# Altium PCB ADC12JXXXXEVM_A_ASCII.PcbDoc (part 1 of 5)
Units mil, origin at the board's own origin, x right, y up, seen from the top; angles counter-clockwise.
Board outline 5739 x 2680 mil, 10 copper layers (Top Layer L1, Gnd-Plane - L2, Signals - L3, Gnd-Plane - L4, Pwr Plane - L5, Signals - L6, Gnd-Plane - L7, Signals - L8, Gnd-Plane - L9, Bottom Layer - L10), stack 57.8 mil thick; 582 components, 343 nets, 1924 pads, 1318 vias.
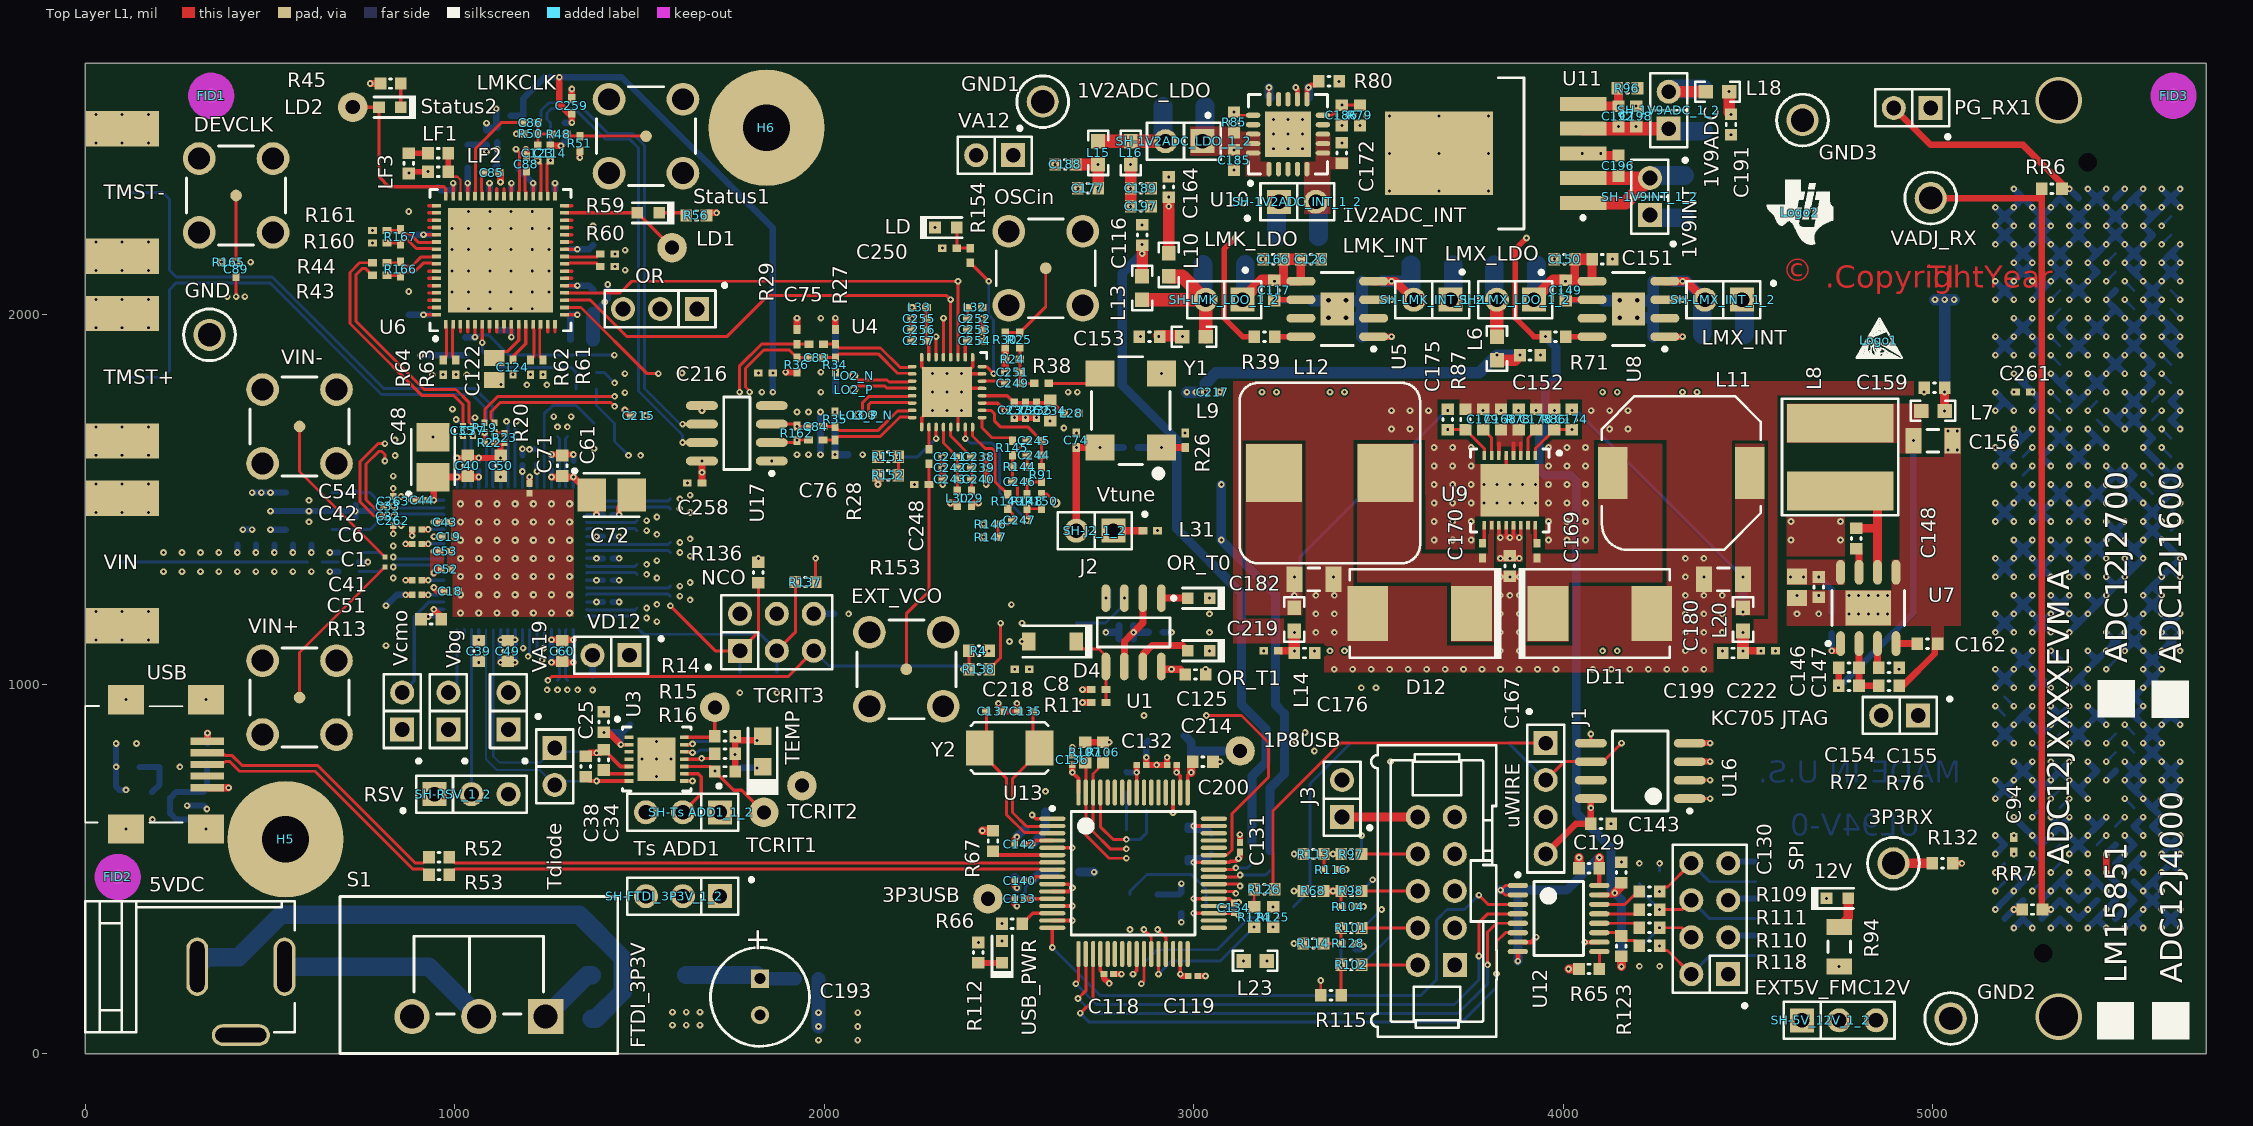
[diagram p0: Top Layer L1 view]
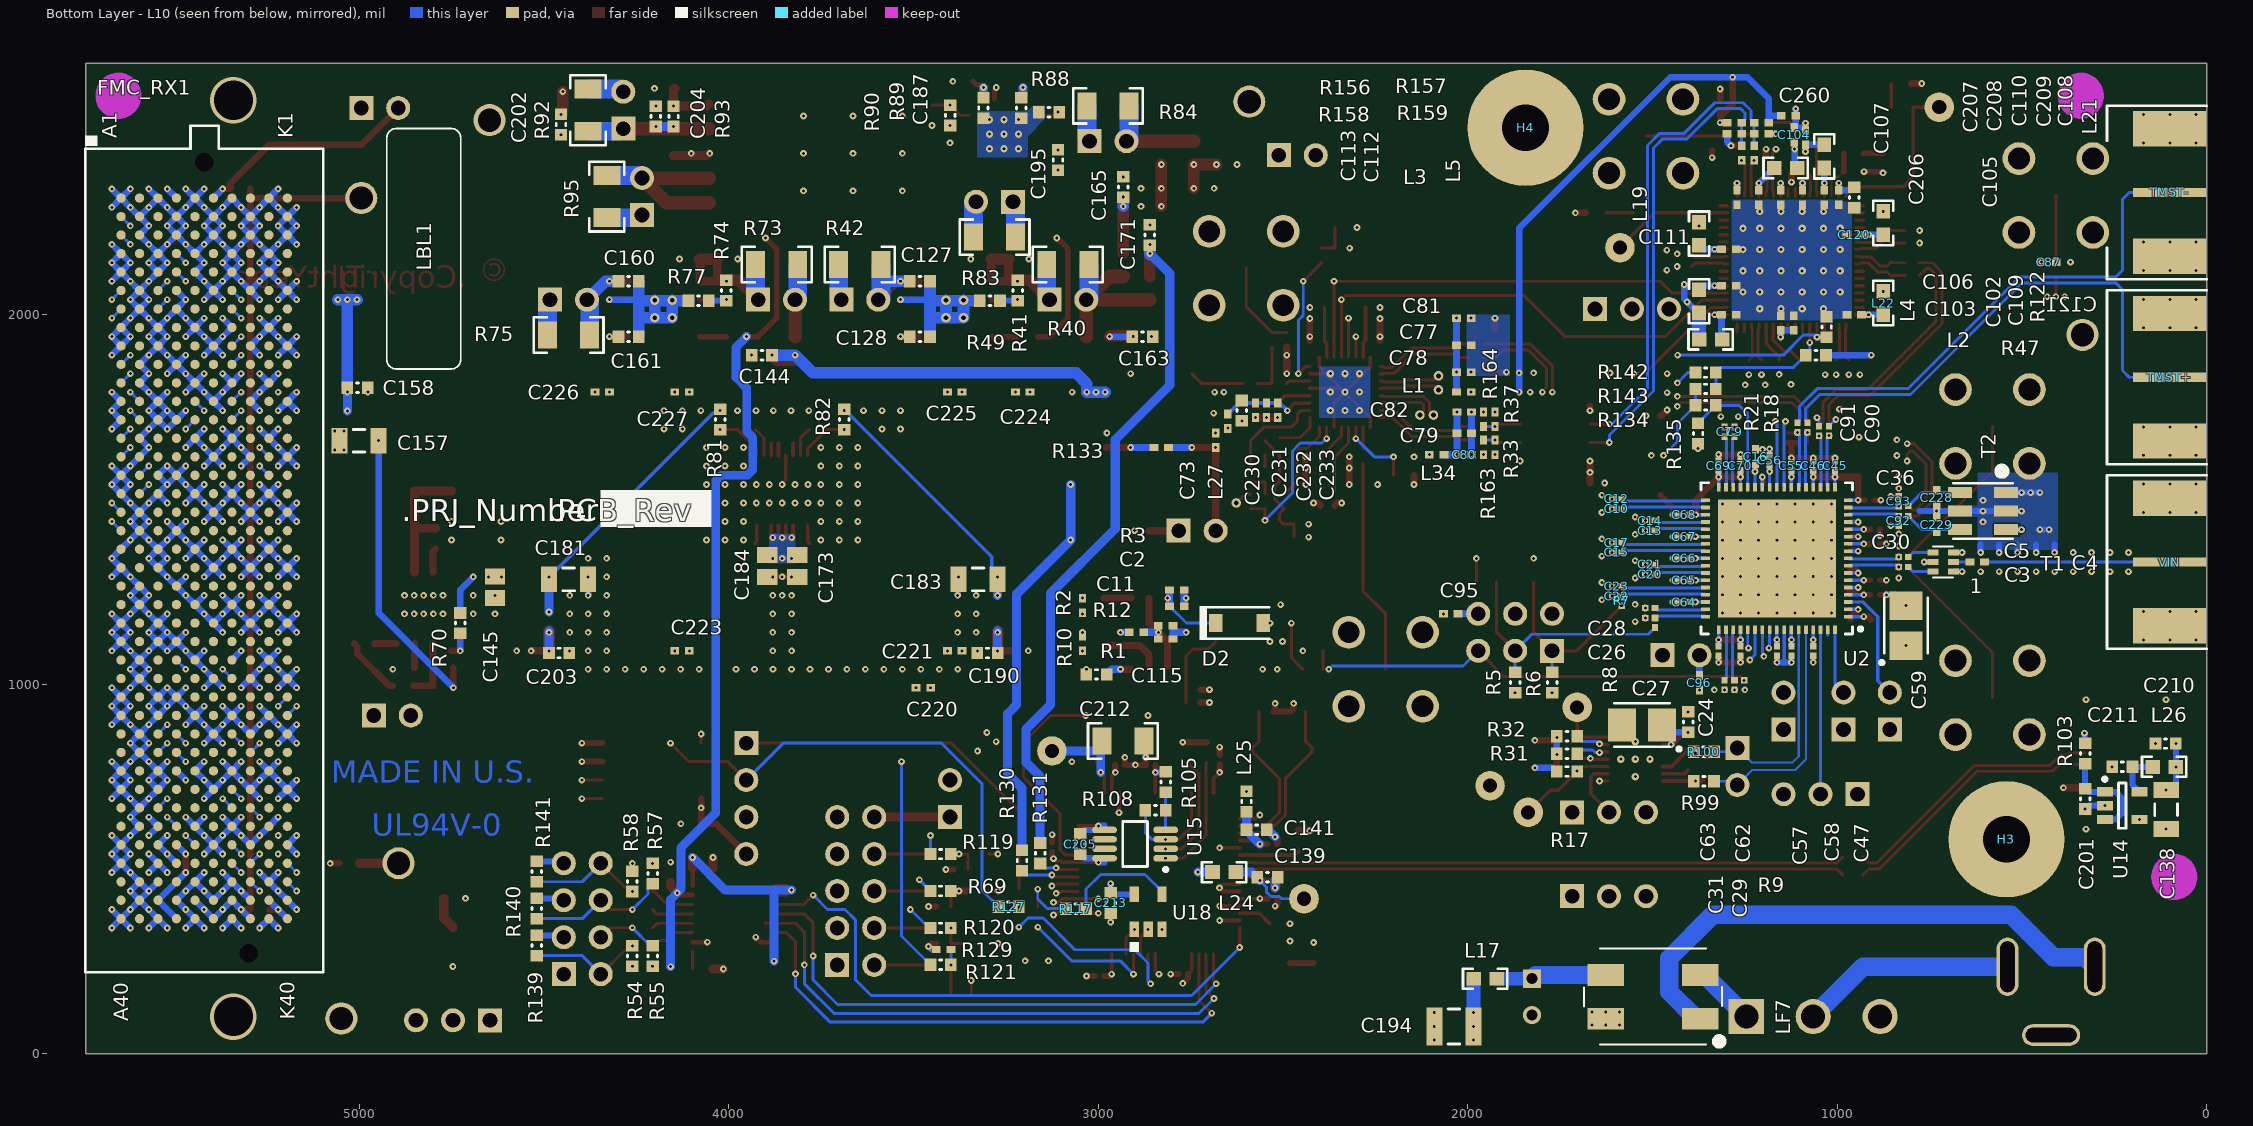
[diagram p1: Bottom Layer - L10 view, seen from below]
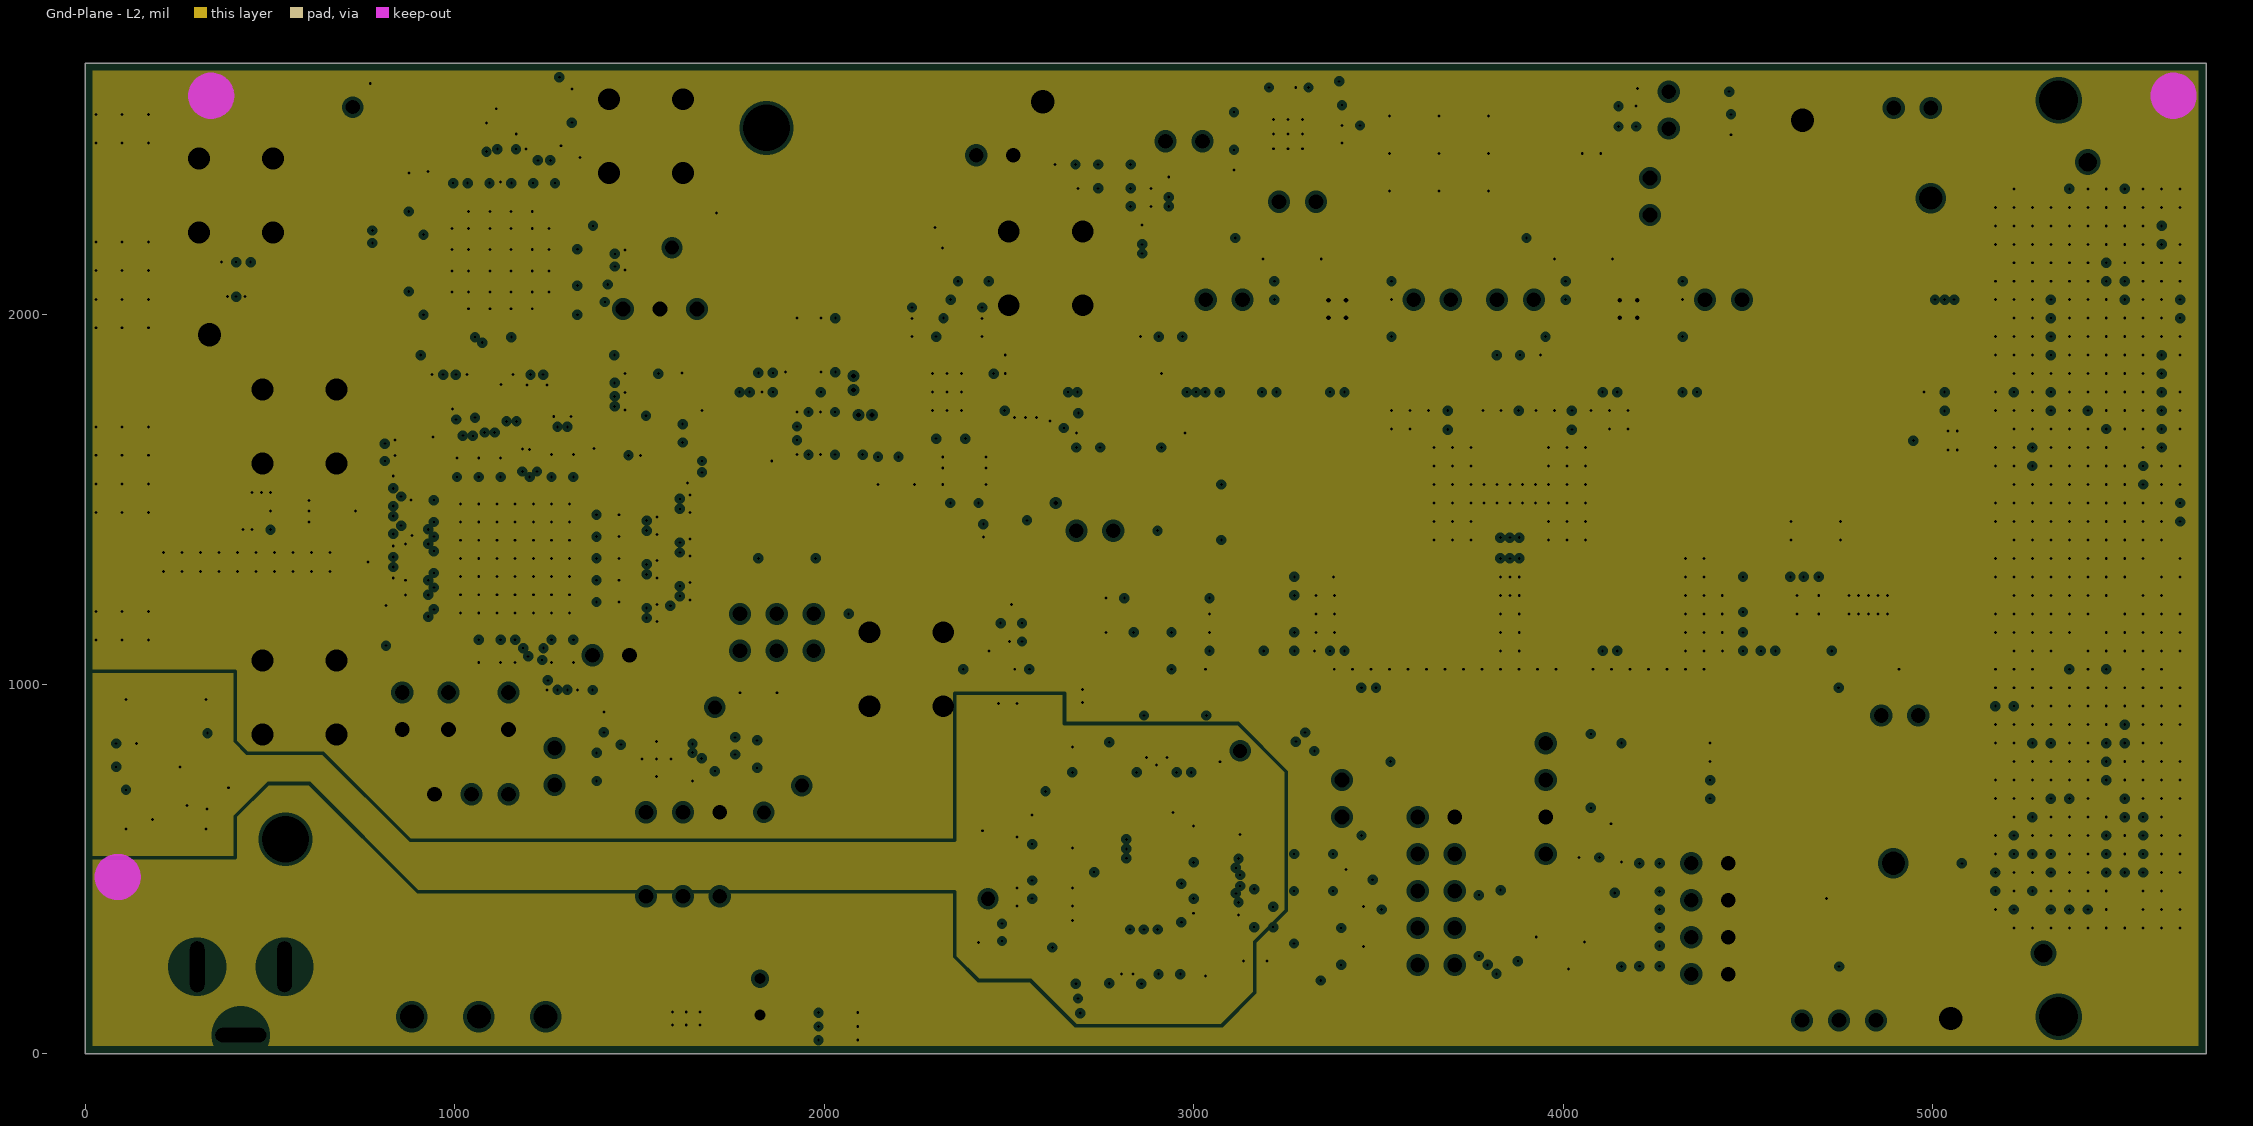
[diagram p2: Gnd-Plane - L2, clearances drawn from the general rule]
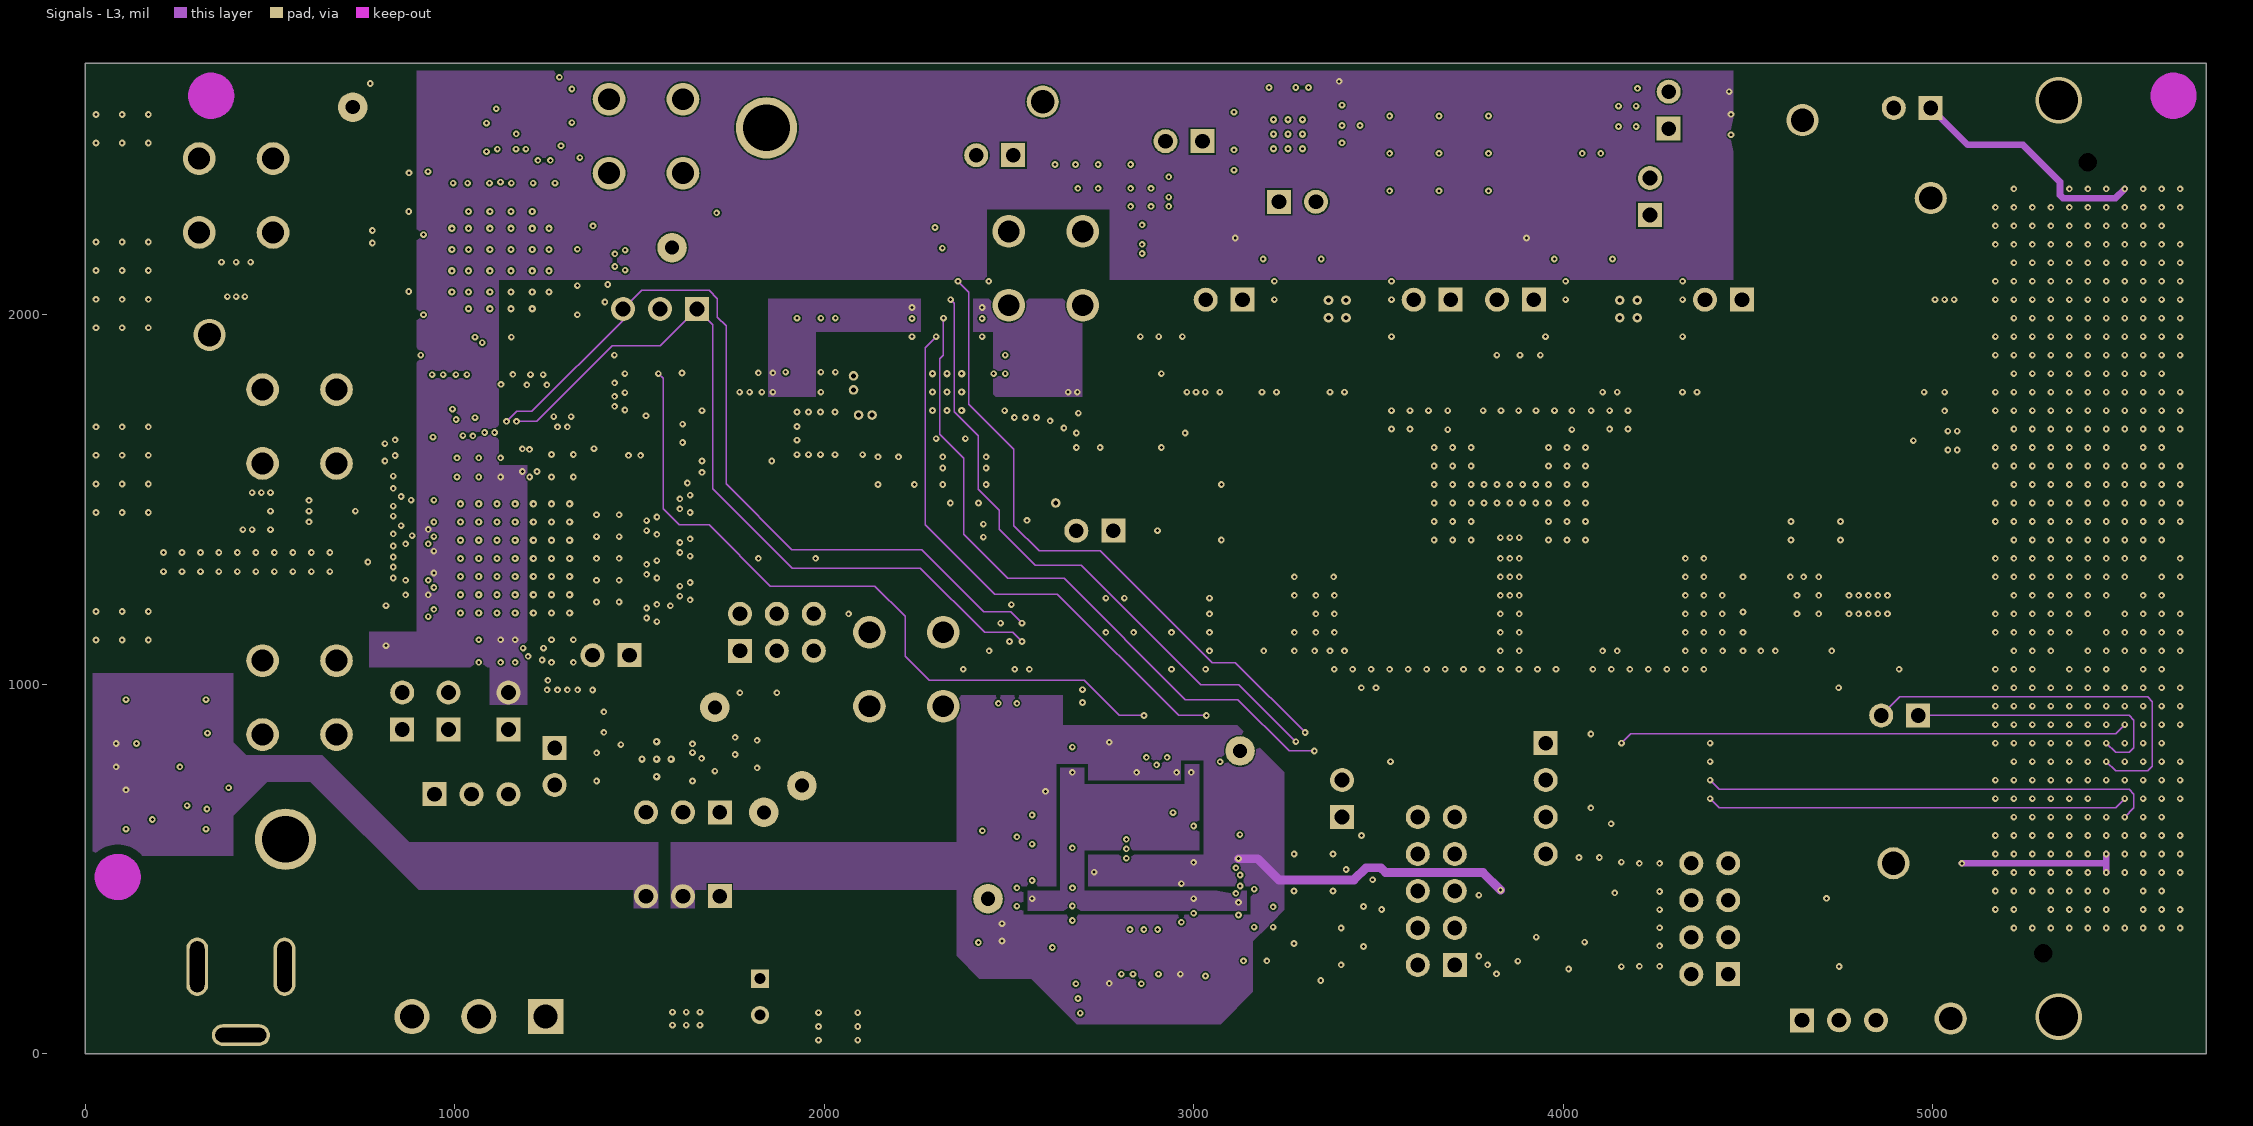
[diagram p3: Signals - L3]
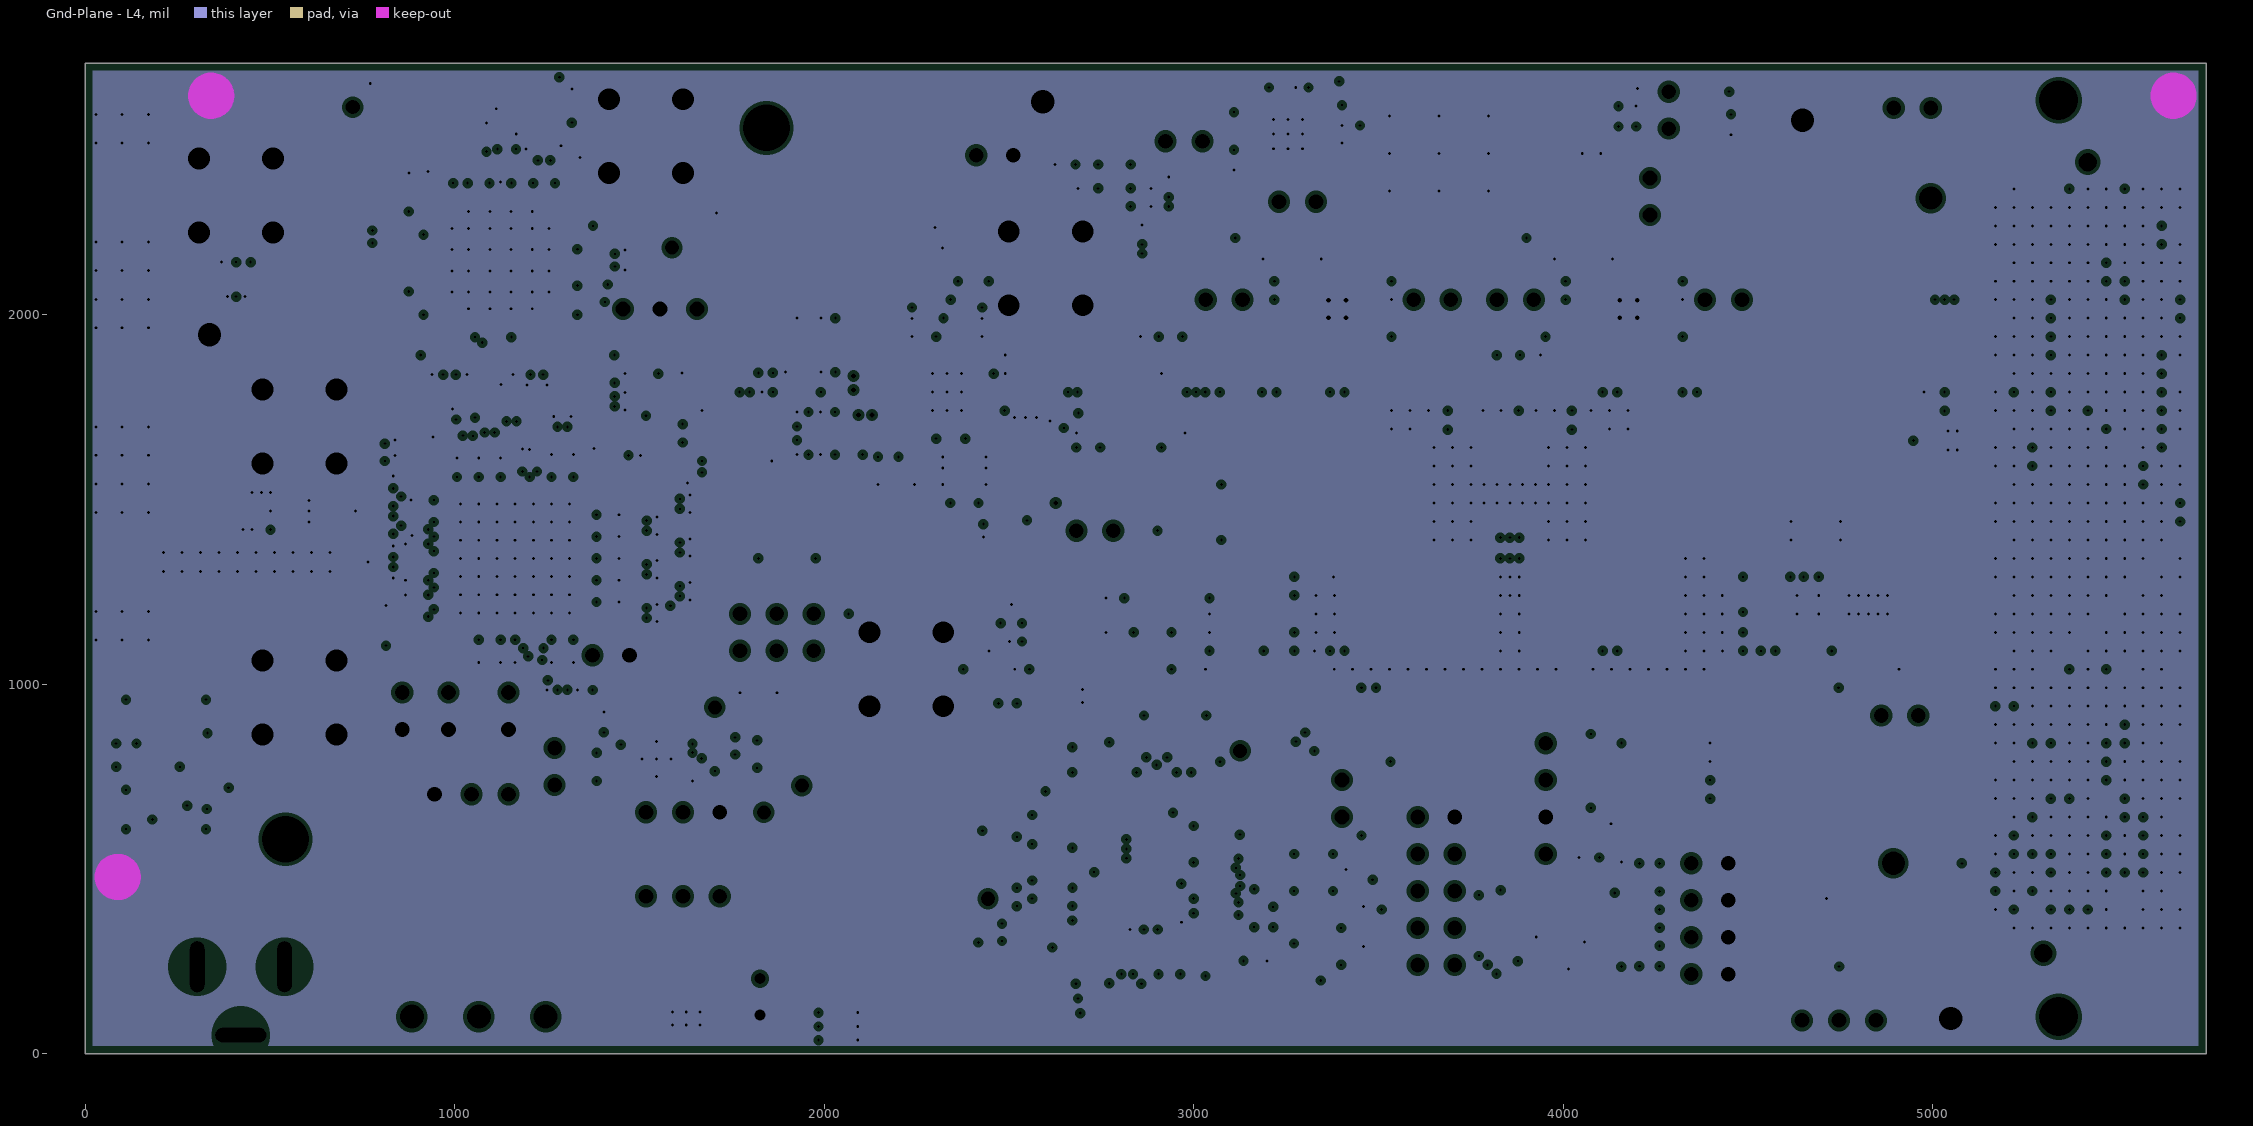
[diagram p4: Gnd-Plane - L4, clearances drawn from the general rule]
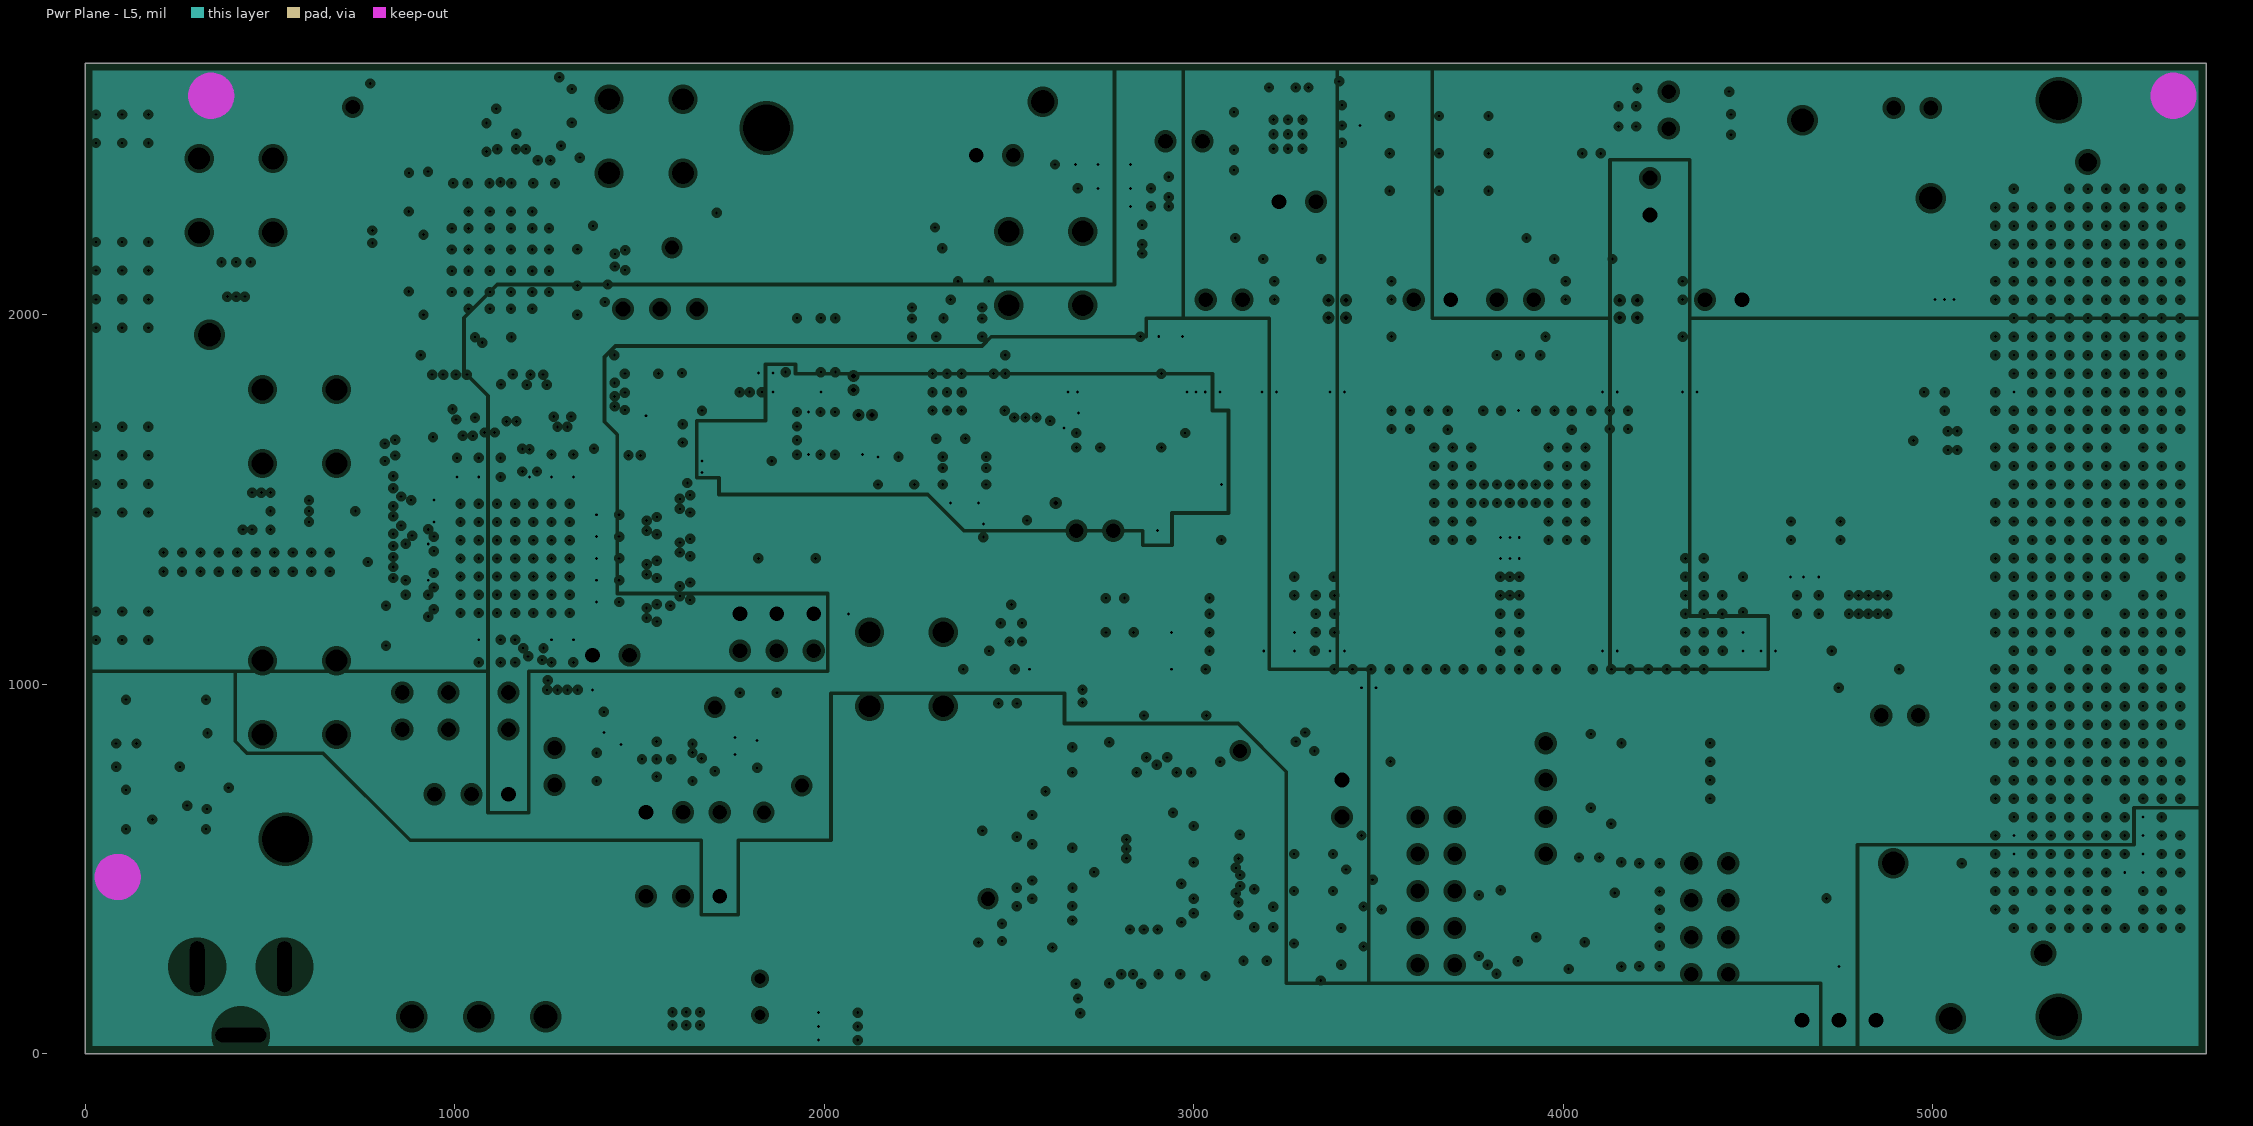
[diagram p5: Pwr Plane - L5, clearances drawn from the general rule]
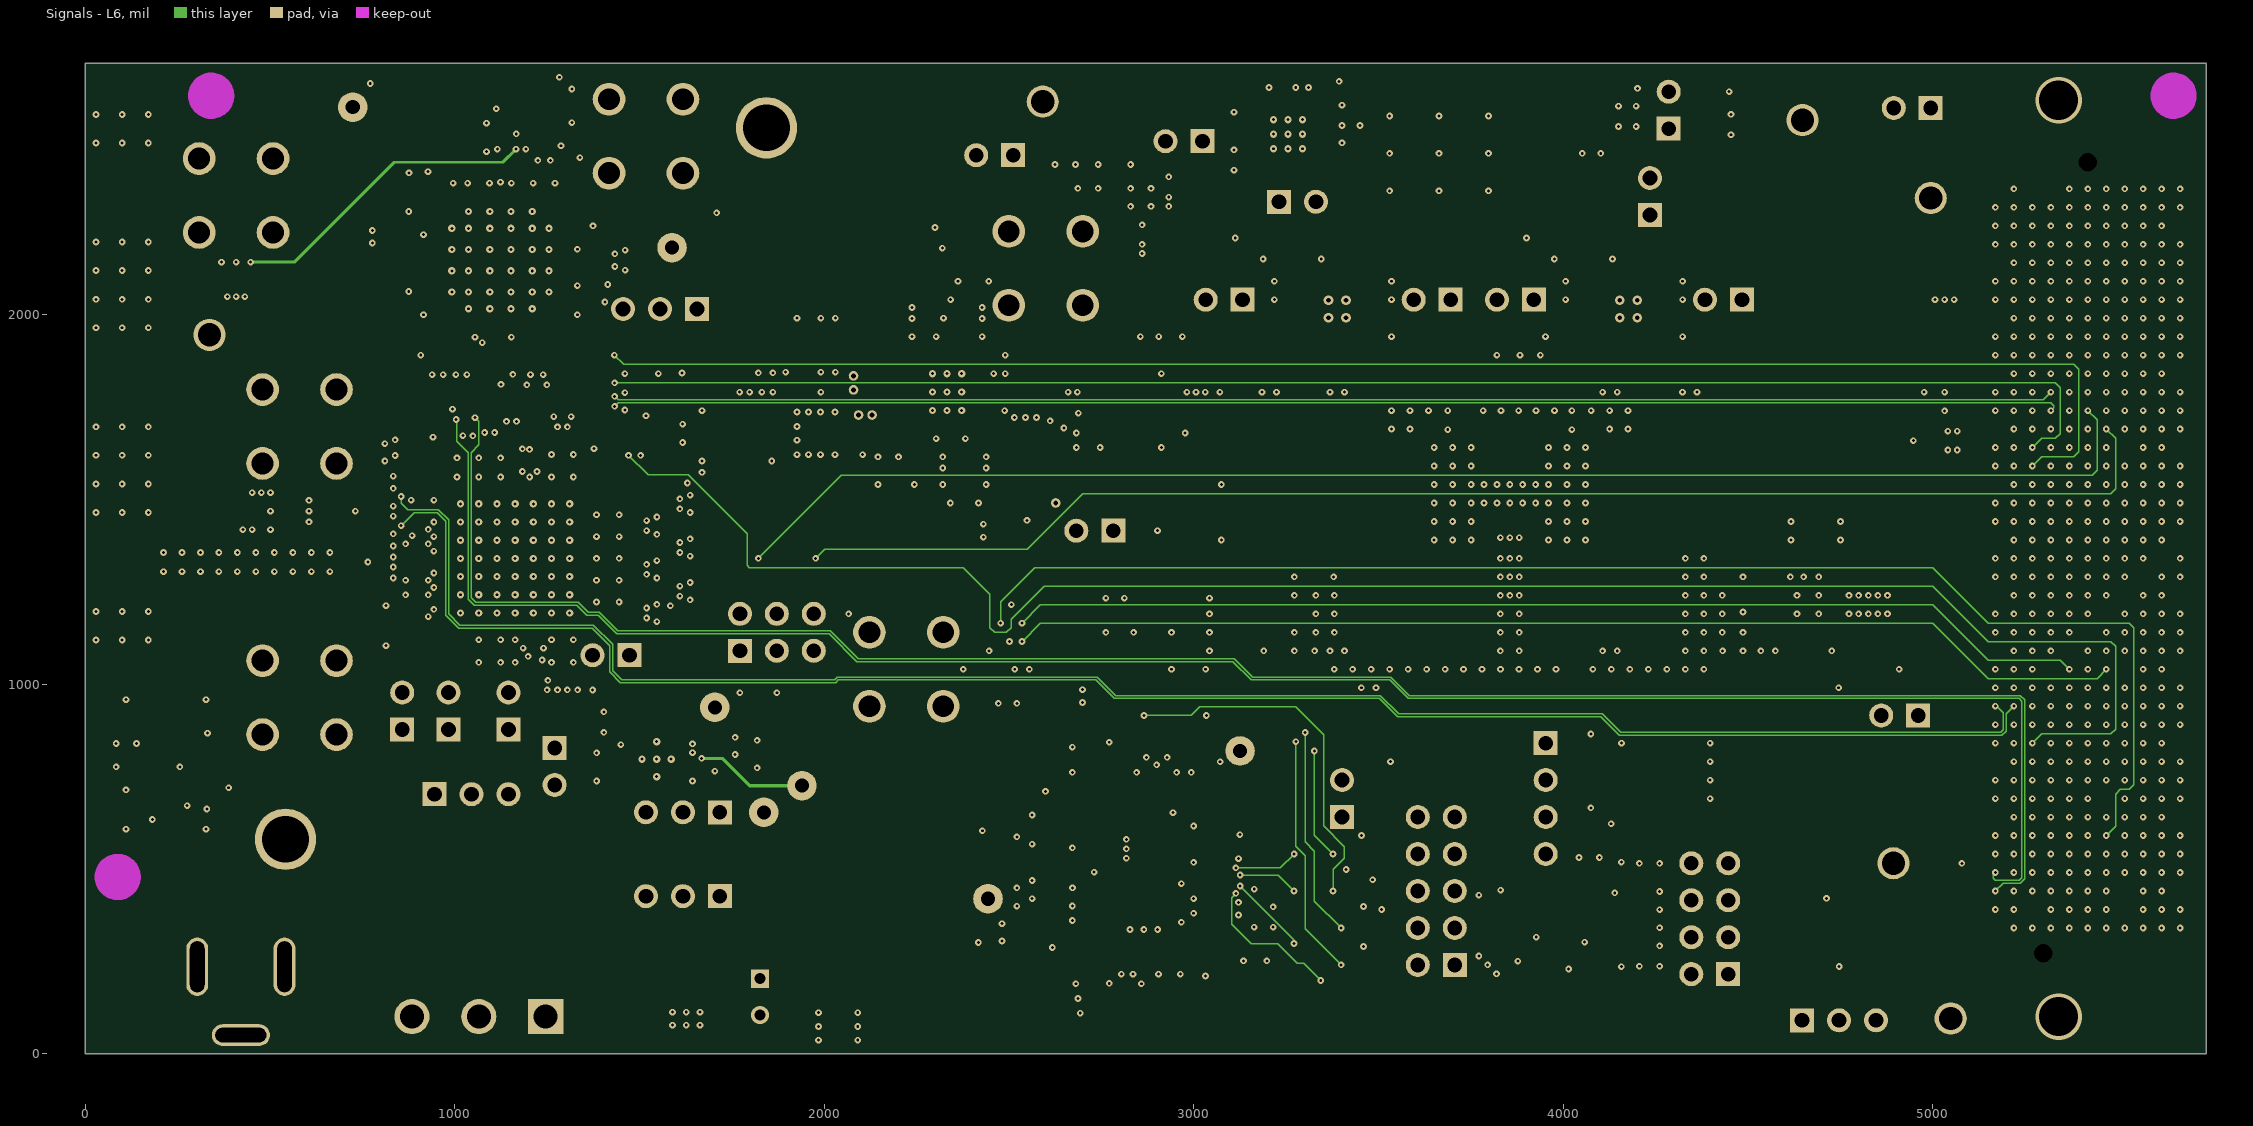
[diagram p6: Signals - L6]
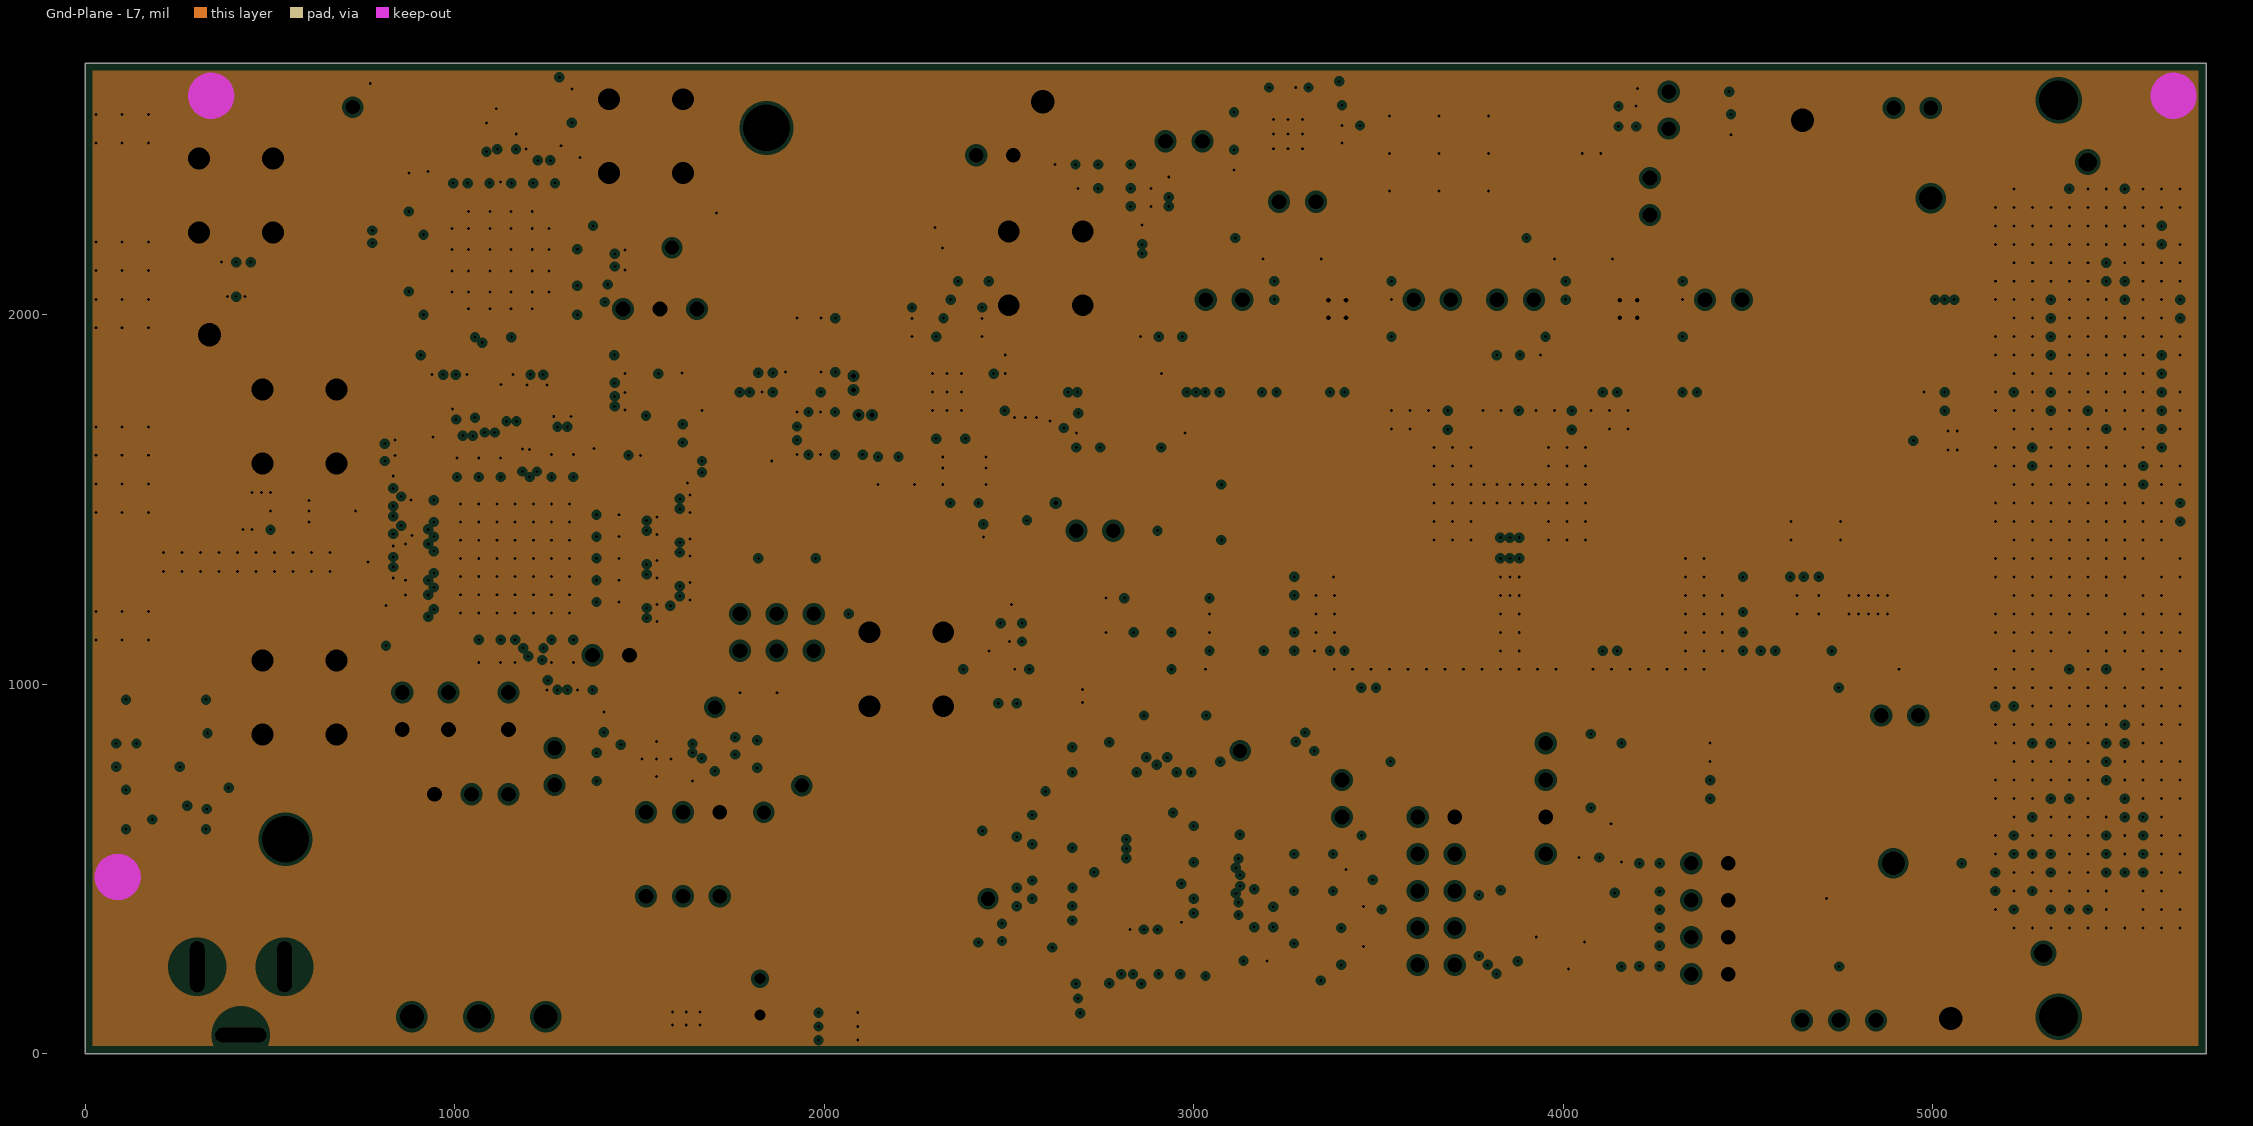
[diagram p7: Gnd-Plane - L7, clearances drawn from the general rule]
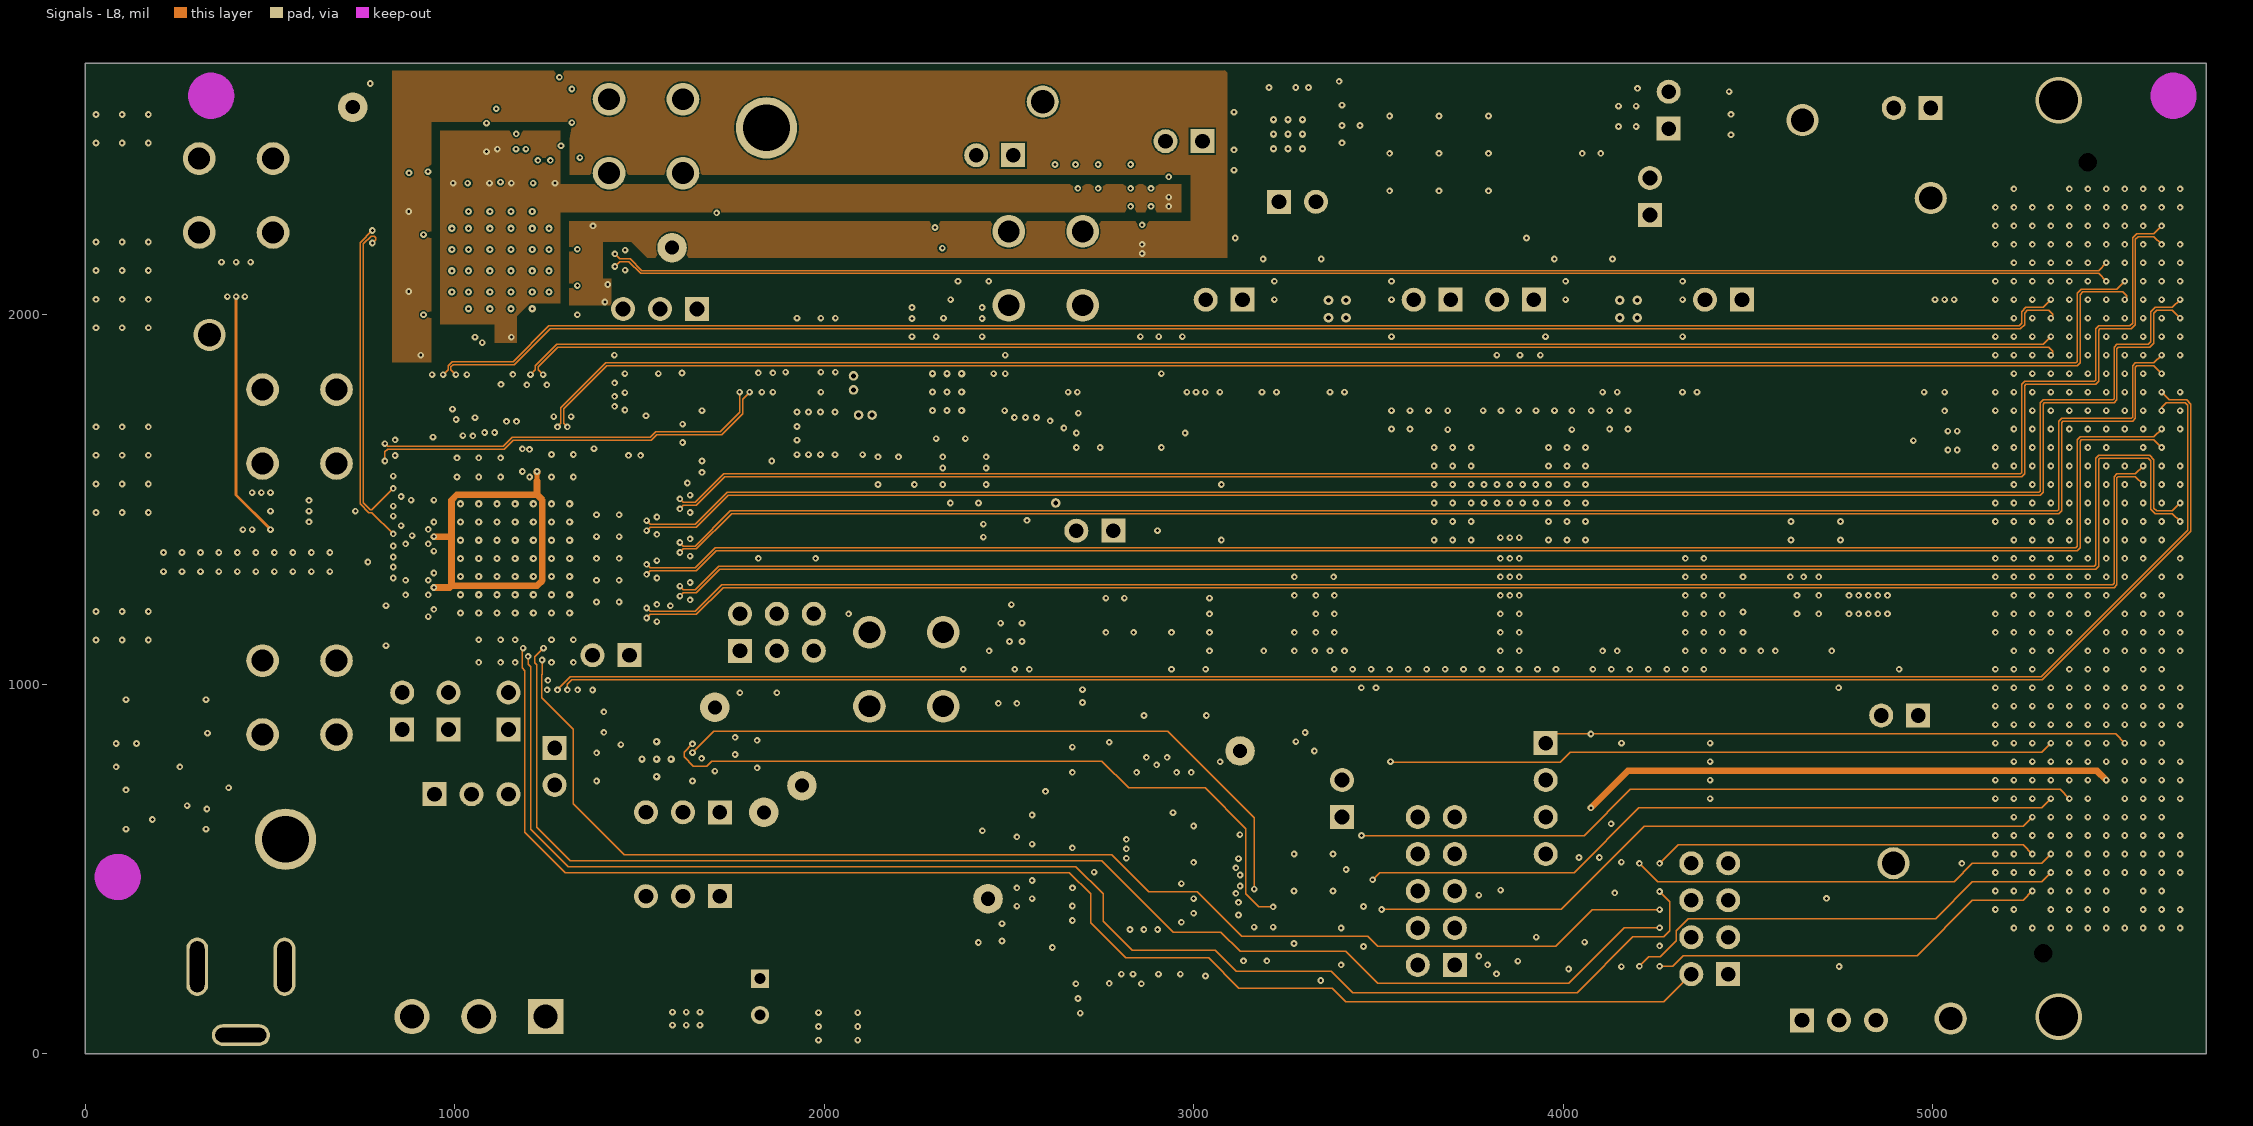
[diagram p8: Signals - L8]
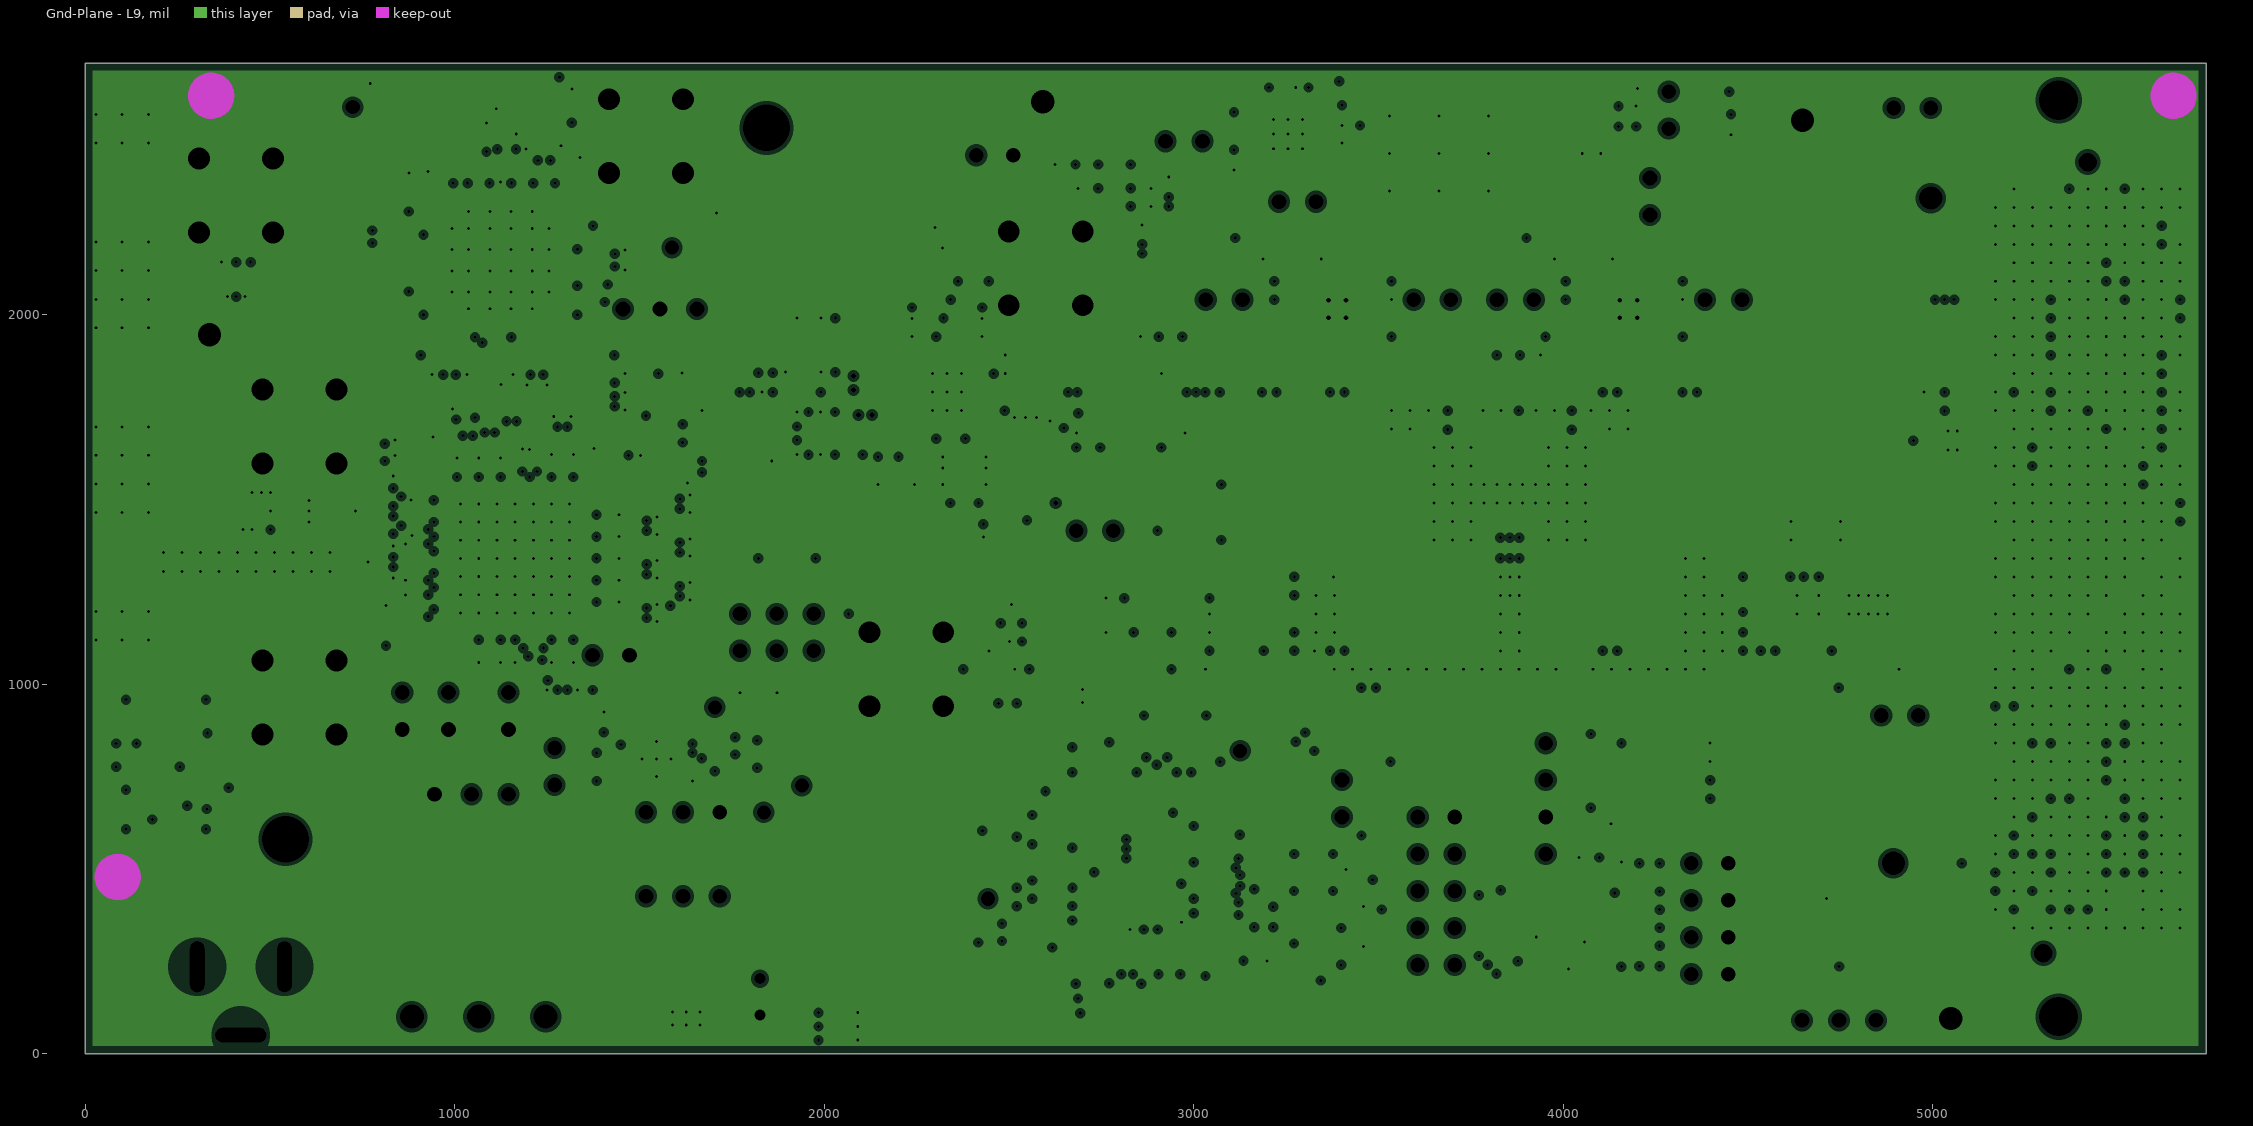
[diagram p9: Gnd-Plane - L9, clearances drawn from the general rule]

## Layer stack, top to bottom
Top Layer L1: signal copper 0.6
Dielectric: core 4, Rogers RO4350, Dk 3.66
Gnd-Plane - L2: plane copper 1.2, net (Multiple Nets)
Dielectric: prepreg 6.7, NP 4000-6, Dk 4.11
Signals - L3: signal copper 0.6
Dielectric: core 6, NP 4000-6, Dk 4.11
Gnd-Plane - L4: plane copper 1.2, net GND
Dielectric: prepreg 4.1, NP 4000-6, Dk 4.11
Pwr Plane - L5: plane copper 1.2, net (Multiple Nets)
Dielectric: core 6, NP 4000-6, Dk 4.11
Signals - L6: signal copper 0.6
Dielectric: prepreg 6.7, NP 4000-6, Dk 4.11
Gnd-Plane - L7: plane copper 1.2, net GND
Dielectric: core 4, Rogers RO4350, Dk 3.66
Signals - L8: signal copper 0.6
Dielectric: prepreg 7.3, Rogers RO4350, Dk 3.66
Gnd-Plane - L9: plane copper 1.2, net GND
Dielectric: core 4, Rogers RO4350, Dk 3.66
Bottom Layer - L10: signal copper 0.6

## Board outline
0,0 5739,0 5739,2680 0,2680

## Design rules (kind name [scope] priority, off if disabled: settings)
AcuteAngle [All] p1: minimum=4.50000000000000E+0001 checktracksonly=FALSE
AssemblyTestPointUsage [All] p1: valid=2
Clearance "0201 PADS" [HasFootprint('0201') vs HasFootprint('0201')] p1: gap=7.87
Clearance Clearance_BoardEdge_MountingHoles [OnCopper and InComponentClass('Mounting Holes') vs IsKeepOut] p2: gap=40
Clearance Clearance_BoardEdge_Poly [OnCopper and InPoly vs IsKeepOut] p3: gap=25
Clearance Clearance_BoardEdge [OnCopper and Not InComponentClass('Logo') and not InComponentClass('FiducialMark') and not InRegion(1000,500,4000,800) and Not IsKeepout vs IsKeepOut] p4: gap=25
Clearance [All] p5: gap=4
ComponentClearance ComponentClearance_1 [HasFootprint('TESTPOINT')] p1: gap=3.5 collisioncheckmode=3 verticalgap=10 showdistances=FALSE
ComponentClearance ComponentClearance_Shared_Pad [(InComponent('R7') OR InComponent('R8') OR InComponent('R9') OR InComponent('C22') OR InComponent('C26') OR InComponent('C29') OR InComponent('SH-*') OR InComponent('RSV*') OR InComponent('Ts ADD1*') OR InComponent('LMX_INT*') OR InComponent('LMX_LDO*') OR InComponent('LMK_INT*') OR InComponent('LMK_LDO*') OR InComponent('1V2ADC_INT*') OR InComponent('1V2ADC_LDO*') OR InComponent('1V9INT*') OR InComponent('1V9ADC*') OR InComponent('+12V*') OR InComponent('C32*') OR InComponent('C262*')OR InComponent('C33*') OR InComponent('C263*') OR InComponent('C92*') OR InComponent('C93*') OR InComponent('C89*') OR InComponent('R165*'))] p2: gap=0 collisioncheckmode=3 verticalgap=0 showdistances=FALSE
ComponentClearance ComponentClearance_0201 [HasFootprint('0201*') or HasFootprint('LQA68A') vs HasFootprint('0201*') or HasFootprint('LQA68A')] p3: gap=10 collisioncheckmode=3 verticalgap=10 showdistances=FALSE
ComponentClearance ComponentClearance_ScrewToNut [(HasFootprint('NY PMS 440 0025 PH')) vs (HasFootprint('Keystone_1902C'))] p4: gap=5 collisioncheckmode=3 verticalgap=10 showdistances=FALSE
ComponentClearance ComponentClearance_MountingHoles [InComponentClass('Mounting Holes')] p5: gap=250 collisioncheckmode=3 verticalgap=100000 showdistances=FALSE
ComponentClearance ComponentClearance_SmallPassives [HasFootprint('0201*') or HasFootprint('0402*') or HasFootprint('0508') or HasFootprint('0603*') or HasFootprint('0612') or HasFootprint('0805*') or HasFootprint('0815*') or HasFootprint('0830*') or HasFootprint('1206*') or HasFootprint('1210*') or HasFootprint('1808*') or HasFootprint('1812*') or HasFootprint('1825*') or HasFootprint('2010*') or HasFootprint('2220*') or HasFootprint('2225*') or HasFootprint('2512*') or HasFootprint('2728*') or HasFootprint('3518*') or HasFootprint('LQA68A*')  or HasFootprint('RTV0032A*') or HasFootprint('DBV0005A*') or HasFootprint('XTAL_ABM3*') or HasFootprint('RGW0020A*') or HasFootprint('M08A*') or HasFootprint('LED_LTST-C190*') or HasFootprint('DDA0008B*') or HasFootprint('SOIJ-SM8*') or HasFootprint('MSOP-MS8*') or HasFootprint('SDA16A*') or HasFootprint('OSC_CWX*') or HasFootprint('3528-21*') or HasFootprint('PW0016A*') or HasFootprint('MRA08A*') or HasFootprint('TJ5A*') or HasFootprint('SOD-123*') or HasFootprint('RLY0068A*') or HasFootprint('SOP-5_.95MM_(DBV)*') vs HasFootprint('0201*') or HasFootprint('0402*') or HasFootprint('0508') or HasFootprint('0603*') or HasFootprint('0612') or HasFootprint('0805*') or HasFootprint('0815*') or HasFootprint('0830*') or HasFootprint('1206*') or HasFootprint('1210*') or HasFootprint('1808*') or HasFootprint('1812*') or HasFootprint('1825*') or HasFootprint('2010*') or HasFootprint('2220*') or HasFootprint('2225*') or HasFootprint('2512*') or HasFootprint('2728*') or HasFootprint('3518*') or HasFootprint('LQA68A*')  or HasFootprint('RTV0032A*') or HasFootprint('DBV0005A*') or HasFootprint('XTAL_ABM3*') or HasFootprint('RGW0020A*') or HasFootprint('M08A*') or HasFootprint('LED_LTST-C190*') or HasFootprint('DDA0008B*') or HasFootprint('SOIJ-SM8*') or HasFootprint('MSOP-MS8*') or HasFootprint('SDA16A*') or HasFootprint('OSC_CWX*') or HasFootprint('3528-21*') or HasFootprint('PW0016A*') or HasFootprint('MRA08A*') or HasFootprint('TJ5A*') or HasFootprint('SOD-123*') or HasFootprint('RLY0068A*') or HasFootprint('SOP-5_.95MM_(DBV)*')] p6: gap=6 collisioncheckmode=3 verticalgap=10 showdistances=FALSE
ComponentClearance ComponentClearance_THtoSMT [IsThruComponent vs IsSMTComponent] p7: gap=10 collisioncheckmode=3 verticalgap=0 showdistances=FALSE
ComponentClearance ComponentClearance_THtoTH [IsThruComponent vs IsThruComponent] p8: gap=10 collisioncheckmode=3 verticalgap=100000 showdistances=FALSE
ComponentClearance [All] p9: gap=10 collisioncheckmode=3 verticalgap=10 showdistances=FALSE
DiffPairsRouting [All] p1: maxlimit=100 minlimit=4 mostfreqgap=4 toplayer_mingap=8 toplayer_prefgap=8 bottomlayer_mingap=8 bottomlayer_prefgap=8 maxuncoupledlength=1000
FabricationTestPointUsage TestPointUsage [All] p1: valid=2 allowmultiple=FALSE
FabricationTestpoint Testpoint [All] p1: side=3 testpointundercomponent=TRUE minsize=40 maxsize=100 preferedsize=60 minholesize=0 maxholesize=40 preferedholesize=32 testpointgrid=1 allowsidetop=TRUE allowsidebottom=TRUE usegrid=TRUE gridtolerance=0.01
FanoutControl Fanout_LCC [IsLCC] p1: bgadir=Out bgaviamode=Centered fanoutstyle=Auto fanoutdirection=Alternating viagrid=1 // Fanout_LCC (Default Rule)
FanoutControl Fanout_BGA [IsBGA] p2: bgadir=Out bgaviamode=Centered fanoutstyle=Auto fanoutdirection=Alternating viagrid=1 // Fanout_BGA (Default Rule)
FanoutControl Fanout_Default [All] p4: bgadir=Out bgaviamode=Centered fanoutstyle=Auto fanoutdirection=Alternating viagrid=1 // Fanout_Default (Default Rule)
FanoutControl Fanout_Small [(CompPinCount < 5)] p5: bgadir=Out bgaviamode=Centered fanoutstyle=Auto fanoutdirection=OutThenIn viagrid=1 // Fanout_Small (Default Rule)
HoleSize [All] p1: absolutevalues=TRUE maxlimit=251 minlimit=7.87 maxpercent=80.000 minpercent=20.000
MinimumAnnularRing [All] p1: minimumring=5
MinimumSolderMaskSliver MinimumSolderMaskSliver_Logo [InComponentClass('Logo') vs InComponentClass('Logo')] p1: minsoldermaskwidth=0.7
MinimumSolderMaskSliver [All] p2: minsoldermaskwidth=4
NetAntennae "NetAntennae U2 or U6" [(InNet('U2-*') OR InNet('U6-*'))] p1: netantennaetolerance=50
NetAntennae [All] p2: netantennaetolerance=0
PlaneClearance [All] p1: clearance=10
PlaneConnect [All] p1: planeconnectstyle=Direct reliefexpansion=10 reliefentries=4 reliefconductorwidth=10 reliefairgap=10
PolygonConnect [All] p1: connectstyle=Direct reliefconductorwidth=10 reliefentries=4 polygonreliefangle="90 Angle" airgapwidth=10
RoutingVias [All] p1: holewidth=16 width=34 viastyle="Through Hole" minholewidth=7.87 minwidth=18 maxholewidth=106 maxwidth=126
SMDToCorner [All] p1: distance=30000
SilkToSilkClearance [All] p1: silktosilkclearance=5
SilkscreenOverComponentPads [All] p1: minsilkscreentomaskgap=5
SolderMaskExpansion [All] p1: expansion=3
Width [All] p1: maxlimit=100 minlimit=4 preferedwidth=10 checkconnectedcopper=TRUE
12 further rules are at their usual default settings.

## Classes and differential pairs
differential pair FMC_DEVCLK: +FMC_DEVCLK_P -FMC_DEVCLK_N
differential pair FMC_SYSREF: +FMC_SYSREF_P -FMC_SYSREF_N
differential pair TRF_OUTB: +TRF_OUTB_P -TRF_OUTB_N
differential pair TRF_OUTA: +TRF_OUTA_P -TRF_OUTA_N
differential pair LO4: +LO4_P -LO4_N
differential pair LO3: +LO3_P -LO3_N
differential pair LO2: +LO2_P -LO2_N
differential pair LO1: +LO1_P -LO1_N
differential pair SYNC~/TMST: +SYNC~/TMST_P -SYNC~/TMST_N
differential pair VIN: +VIN_P -VIN_N
differential pair SYSRF: +SYSRF_P -SYSRF_N
differential pair SYSREFTX: +SYSREFTX_P -SYSREFTX_N
differential pair SYSREFRX: +SYSREFRX_P -SYSREFRX_N
differential pair SYNC: +SYNC_P -SYNC_N
differential pair DEVCLK: +DEVCLK_P -DEVCLK_N
differential pair DEVCLKBRX: +DEVCLKBRX_P -DEVCLKBRX_N
differential pair DEVCLKARX: +DEVCLKARX_P -DEVCLKARX_N
differential pair D7: +D7_P -D7_N
differential pair D6: +D6_P -D6_N
differential pair D5: +D5_P -D5_N
differential pair D4: +D4_P -D4_N
differential pair D3: +D3_P -D3_N
differential pair D2: +D2_P -D2_N
differential pair D1: +D1_P -D1_N
differential pair D0: +D0_P -D0_N
differential pair CLKIN1: +CLKIN1_P -CLKIN1_N
differential pair CLK4: +CLK4_P -CLK4_N
differential pair CLK0: +CLK0_P -CLK0_N
differential pair CLK11: +CLK11_P -CLK11_N
differential pair CLK3: +CLK3_P -CLK3_N
differential pair TMST: +TMST_P -TMST_N
differential pair CLK10: +CLK10_P -CLK10_N
differential pair DEV_CLK: +DEV_CLK_P -DEV_CLK_N

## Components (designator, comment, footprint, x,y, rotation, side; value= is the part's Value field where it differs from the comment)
1P8USB "TESTPOINT" TESTPOINT#1 3125,819 r90 top
1V2ADC_INT "TSW-102-07-G-S" TSW-102-07-G-S 3280.26,2305 r0 top
1V2ADC_LDO "TSW-102-07-G-S" TSW-102-07-G-S 2973.27,2469 r180 top
1V9ADC "TSW-102-07-G-S" TSW-102-07-G-S 4285,2552.93 r90 top
1V9INT "TSW-102-07-G-S" TSW-102-07-G-S 4234,2319.07 r90 top
3P3RX "5011" Keystone5011 4893,515 r90 top
3P3USB "TESTPOINT" TESTPOINT#1 2443,419 r90 top
5VDC "PJ-202AH" CONN_CUI-PJ-202AH 539.37,235 r180 top
12V "LTST-C190GKT" LED_LTST-C190 4741.47,420 r180 top
C1 "GRM033R71C101KA01D" 0201L 822.55,1316.66 r180 top
C2 "GRM155R71A104KA01D" 0402L#1 2787,1210.67 r180 bottom
C3 "GRM033R71C101KA01D" 0201#1 820.58,1316.66 r180 bottom
C4 "GRM1555C1H100JA01D" 0402L#1 621,1330.16 r180 bottom
C5 "GRM033R71C101KA01D" 0201#1 820.58,1343.66 r180 bottom
C6 "GRM033R71C101KA01D" 0201L 822.55,1343.66 r0 top
C7 "C0603X5R0J104K" 0201#1 1304.84,1682.81 r270 bottom
C8 "GRM155R71A104KA01D" 0402L#1 2742.32,985 r180 top
C9 "C0603X5R0J104K" 0201#1 1277.84,1682.81 r270 bottom
C10 "C0603X5R0J104K" 0201#1 1596.19,1474.14 r180 bottom
C11 "GRM155R71A104KA01D" 0402L#1 2817.32,1158 r180 bottom
C12 "C0603X5R0J104K" 0201#1 1596.19,1501.14 r180 bottom
C13 "C0603X5R0J104K" 0201#1 1506.19,1415.08 r180 bottom
C14 "C0603X5R0J104K" 0201#1 1506.19,1442.08 r180 bottom
C15 "C0603X5R0J104K" 0201#1 1596.19,1356.03 r180 bottom
C16 "C1005X5R0J475M050BC" 0402L#1 1221,1615.62 r270 bottom
C17 "C0603X5R0J104K" 0201#1 1596.19,1383.03 r180 bottom
C18 "C1005X5R1A104K" 0402L#1 988.26,1251.2 r180 top
C19 "C1005X5R1A104K" 0402L#1 983.2,1399.05 r180 top
C20 "C0603X5R0J104K" 0201#1 1506.19,1296.97 r180 bottom
C21 "C0603X5R0J104K" 0201#1 1506.19,1323.97 r180 bottom
C22 "C0603X5R0J104K" 0201#1 1596.19,1237.92 r180 bottom
C23 "C0603X5R0J104K" 0201#1 1596.19,1264.92 r180 bottom
C24 "0603YC104JAT2A" 0603L#1 1403.28,897.03 r90 bottom
C25 "06035A101JAT2A" 0603L#1 1403.28,897.03 r90 top
C26 "C0603X5R0J104K" 0201#1 1506.19,1178.86 r180 bottom
C27 "293D106X0010B2TE3" 3528-21 1528.28,889.42 r0 bottom
C28 "C0603X5R0J104K" 0201#1 1506.19,1205.86 r180 bottom
C29 "C0603X5R0J104K" 0201#1 1277.84,997.19 r90 bottom
C30 "C0603X5R0J224M" 0201#1 820.58,1454.45 r180 bottom
C31 "C0603X5R0J104K" 0201#1 1304.84,997.19 r90 bottom
C32 "GRM033R61A472KA01D" 0201#1 820.58,1454.45 r180 top
C33 "GRM033R61A472KA01D" 0201#1 820.58,1481.45 r180 top
C34 "06035A101JAT2A" 0603L#1 1403.28,795 r90 top
C35 "GRM033R61A472KA01D" 0201#1 1021.93,1685 r90 top
C36 "C0603X5R0J224M" 0201#1 820.58,1481.45 r180 bottom
C37 "GRM033R61A472KA01D" 0201#1 1048.93,1685 r90 top
C38 "06035A101JAT2A" 0603L#1 1354.28,777 r90 top
C39 "C1608X5R1A105K" 0603L#1 1064.96,1089.26 r270 top
C40 "C1608X5R1A105K" 0603L#1 1035.43,1590.74 r90 top
C41 "C0603X5R0J104K" 0201#1 897.65,1280.94 r0 top
C42 "C0603X5R0J104K" 0201#1 897.65,1379.37 r0 top
C43 "C0603X5R0J104K" 0201#1 973.87,1438.43 r180 top
C44 "C0603X5R0J104K" 0201#1 912.65,1497.48 r0 top
C45 "C0603X5R0J104K" 0201#1 1005.91,1590.74 r270 bottom
C46 "C0603X5R0J104K" 0201#1 1064.96,1590.74 r270 bottom
C47 "C0603X5R0J104K" 0201#1 1064.96,1089.26 r90 bottom
C48 "293D106X0010B2TE3" 3528-21 941,1614 r90 top
C49 "C1608X5R1A105K" 0603L#1 1143.7,1089.26 r270 top
C50 "C1608X5R1A105K" 0603L#1 1124.02,1590.74 r90 top
C51 "C0603X5R0J104K" 0201#1 897.65,1241.57 r0 top
C52 "C0603X5R0J104K" 0201#1 976.57,1310.95 r180 top
C53 "C0603X5R0J104K" 0201#1 973.87,1359.68 r180 top
C54 "C0603X5R0J104K" 0201#1 897.65,1418.74 r0 top
C55 "C0603X5R0J104K" 0201#1 1124.02,1590.74 r270 bottom
C56 "C0603X5R0J104K" 0201#1 1183.07,1605.74 r270 bottom
C57 "C0603X5R0J104K" 0201#1 1163.39,1089.26 r90 bottom
C58 "C0603X5R0J104K" 0201#1 1124.02,1089.26 r90 bottom
C59 "293D106X0010B2TE3" 3528-21 814,1158 r90 bottom
C60 "C1608X5R1A105K" 0603L#1 1291.34,1089.26 r270 top
C61 "C1608X5R1A105K" 0603L#1 1291.34,1590.74 r90 top
C62 "C0603X5R0J104K" 0201#1 1261.81,1089.26 r90 bottom
C63 "C0603X5R0J104K" 0201#1 1320.87,1089.26 r90 bottom
C64 "C0603X5R0J104K" 0201#1 1414.13,1221.89 r180 bottom
C65 "C0603X5R0J104K" 0201#1 1414.13,1280.95 r180 bottom
C66 "C0603X5R0J104K" 0201#1 1414.13,1340 r180 bottom
C67 "C0603X5R0J104K" 0201#1 1414.13,1399.05 r180 bottom
C68 "C0603X5R0J104K" 0201#1 1414.13,1458.11 r180 bottom
C69 "C0603X5R0J104K" 0201#1 1320.87,1590.74 r270 bottom
C70 "C0603X5R0J104K" 0201#1 1261.81,1590.74 r270 bottom
C71 "C0603X5R0J104K" 0201#1 1202.76,1529.51 r90 top
C72 "293D106X0010B2TE3" 3528-21 1424.39,1511.4 r0 top
C73 "C1005X5R1A104K" 0402L#1 2682,1659.68 r270 bottom
C74 "GRM1555C1E101JA01D" 0402L#1 2682,1659.68 r270 top
C75 "GRM1555C1H470JA01D" 0402L#1 1978.05,1919.81 r180 top
C76 "GRM1555C1H470JA01D" 0402L#1 1977.05,1660.18 r180 top
C77 "GRM155R71E103KA01D" 0402L#1 2010.36,1917 r180 bottom
C78 "GRM1555C1H270JA01D" 0402L#1 2010.36,1843.81 r180 bottom
C79 "GRM155R71E103KA01D" 0402L#1 2009.36,1678.5 r180 bottom
C80 "GRM1555C1H270JA01D" 0402L#1 2009.36,1620.82 r180 bottom
C81 "C1005X5R0J105M" 0402L#1 2010.36,1990 r180 bottom
C82 "C1005X5R0J105M" 0402L#1 2009.36,1736.18 r180 bottom
C83 "GRM1555C1H470JA01D" 0402L#1 1978.05,1883.18 r180 top
C84 "GRM1555C1H470JA01D" 0402L#1 1977.05,1696.81 r180 top
C85 "C1005X5R1A104K" 0402L#1 1100,2384 r180 top
C86 "C1005X5R1A104K" 0402L#1 1204.98,2519 r180 top
C87 "C1005X5R1A104K" 0402L#1 427.99,2141.68 r180 bottom
C88 "C1005X5R1A104K" 0402L#1 1194,2407 r90 top
C89 "C1005X5R1A104K" 0402L#1 408.31,2122 r270 top
C90 "GRM033R61A472KA01D" 0201#1 1021.93,1685 r90 bottom
C91 "GRM033R61A472KA01D" 0201#1 1048.93,1685 r90 bottom
C92 "GRM033R61A472KA01D" 0201#1 833.57,1441.46 r270 bottom
C93 "GRM033R61A472KA01D" 0201#1 833.57,1494.45 r90 bottom
C94 "GRM155R71A104KA01D" 0402L#1 5219,565 r270 top
C95 "GRM155R71A104KA01D" 0402L#1 2046,1190 r180 bottom
C96 "GRM155R71A104KA01D" 0402L#1 1373,1003.5 r90 bottom
C102 "C1005X7R1C103K" 0402L#1 1153.09,1977.24 r90 bottom
C103 "C1005X5R1A104K" 0402L#1 1293.32,1999.36 r180 bottom
C104 "C1005X5R1A104K" 0402L#1 1116.05,2486.05 r90 bottom
C105 "C1005X5R1A104K" 0402L#1 1212.14,2316.76 r270 bottom
C106 "C1005X5R1A104K" 0402L#1 1293.32,2078.1 r180 bottom
C107 "C1005X5R1A104K" 0402L#1 1085.92,2479.18 r90 bottom
C108 "C1608X5R1C105K" 0603L#1 953.92,2316.76 r270 bottom
C109 "C1005X5R1A104K" 0402L#1 1117.72,1977.24 r90 bottom
C110 "C1005X5R1A104K" 0402L#1 1034.98,2316.76 r270 bottom
C111 "C1005X5R1A104K" 0402L#1 1293.32,2176.53 r180 bottom
C112 "C1005X5R1A104K" 0402L#1 1224.67,2437 r90 bottom
C113 "C1005X5R1A104K" 0402L#1 1258.67,2437 r90 bottom
C114 "C1005X5R1A104K" 0402L#1 1258.67,2437 r270 top
C115 "0603YC104JAT2A" 0603L#1 3004.49,1026 r0 bottom
C116 "06033C104JAT2A" 0603L#1 2860,2215 r90 top
C117 "06035A331JAT2A" 0603L#1 3218,2065 r270 top
C118 "C0603X5R0J104K" 0201#1 2769.72,215.03 r0 top
C119 "C0603X5R0J104K" 0201#1 2997.47,210.03 r0 top
C120 "C1005X5R1A104K" 0402L#1 953.8,2215.9 r0 bottom
C121 "C1005X5R1A104K" 0402L#1 953.8,1999.36 r0 bottom
C122 "C0805C106K8PACTU" 0805L 1106.9,1852.74 r270 top
C123 "C1005X5R1A104K" 0402L#1 1224.67,2437 r90 top
C124 "C1005X5R1A104K" 0402L#1 1157.3,1857.74 r270 top
C125 "C1608X5R1A105K" 0603L#1 3004.49,1026 r0 top
C126 "06033C104JAT2A" 0603L#1 3317.13,2150 r0 top
C127 "C0603C475K8PACTU" 0603L#1 3482.49,2090 r180 bottom
C128 "06031C103MAT2A" 0603L#1 3482.49,1940 r180 bottom
C129 "06033C104JAT2A" 0603L#1 4069.68,502.06 r180 top
C130 "06033C104JAT2A" 0603L#1 4157,490.31 r90 top
C131 "C0603X5R0J104K" 0201#1 3124.45,558.42 r90 top
C132 "C0603X5R0J104K" 0201#1 2858.31,781.24 r0 top
C133 "C0603X5R0J104K" 0201#1 2528.45,419.1 r180 top
C134 "C0603X5R0J104K" 0201#1 3108.45,394.5 r270 top
C135 "GRM1555C1H180JA01D" 0402L#1 2544.97,926 r180 top
C136 "C0603X5R0J104K" 0201#1 2671,795.02 r90 top
C137 "GRM1555C1H180JA01D" 0402L#1 2457.98,926 r0 top
C138 "GRM31CR60J107ME39L" 1206L 110.24,660.39 r270 bottom
C139 "C1608X5R1A106M" 0603L#1 2541.75,477.1 r180 bottom
C140 "C0603X5R0J104K" 0201#1 2528.45,468.32 r180 top
C141 "C1608X5R1A106M" 0603L#1 2571,606 r180 bottom
C142 "C0603X5R0J104K" 0201#1 2528.45,566.74 r180 top
C143 "C1608X5R1A105K" 0603L#1 4101.7,622 r0 top
C144 "06033C104JAT2A" 0603L#1 3910,1890 r0 bottom
C145 "EMK212BJ106KG-T" 0805L 4632,1262 r270 bottom
C146 "EMK212BJ106KG-T" 0805L 4632,1262 r270 top
C147 "06033C104JAT2A" 0603L#1 4691,1262 r270 top
C148 "06033C104JAT2A" 0603L#1 4792.27,1394 r270 top
C149 "06035A331JAT2A" 0603L#1 4006,2065 r270 top
C150 "C1608X5R1A106M" 0603L#1 4003,2150 r180 top
C151 "06033C104JAT2A" 0603L#1 4105.13,2150 r0 top
C152 "C1608X5R1A106M" 0603L#1 3910,1890 r0 top
C153 "06033C104JAT2A" 0603L#1 2880,1940 r180 top
C154 "06035A100JAT2A" 0603L#1 4772.44,1044 r180 top
C155 "C1608X5R1C105K" 0603L#1 4881,1044 r0 top
C156 "GRM31CR60J476ME19L" 1206L 5000,1658.75 r180 top
C157 "GRM31CR60J476ME19L" 1206L 5000,1658.75 r180 bottom
C158 "C1608X5R1A106M" 0603L#1 5003.94,1802 r180 bottom
C159 "06033C104JAT2A" 0603L#1 5003.94,1802 r180 top
C160 "C0603C475K8PACTU" 0603L#1 4270.49,2090 r180 bottom
C161 "06031C103MAT2A" 0603L#1 4270.49,1940 r180 bottom
C162 "GRM188R71E332KA01D" 0603L#1 4985,1109.54 r0 top
C163 "C1608X5R1A106M" 0603L#1 2880,1940 r180 bottom
C164 "06033C104JAT2A" 0603L#1 2932,2345.06 r90 top
C165 "C1608X5R1A106M" 0603L#1 2932,2345.06 r90 bottom
C166 "C1608X5R1A106M" 0603L#1 3215,2150 r180 top
C167 "06033C104JAT2A" 0603L#1 3855,1319.27 r270 top
C168 "C1608X7R1C224K" 0603L#1 3831,1716 r90 top
C169 "GRM155R60J104KA01D" 0402L#1 3928.74,1361 r270 top
C170 "GRM155R60J104KA01D" 0402L#1 3781.26,1361 r90 top
C171 "C1608X5R1A106M" 0603L#1 2860,2215 r90 bottom
C172 "C1608X5R1A106M" 0603L#1 3400.67,2437 r90 top
C173 "EMK212BJ106KG-T" 0805L 3814.5,1319.27 r270 bottom
C174 "GRM188R71C273KA01D" 0603L#1 4023,1716 r90 top
C175 "GRM188R71C273KA01D" 0603L#1 3687,1716 r270 top
C176 "06033C104JAT2A" 0603L#1 3299.41,1084 r0 top
C177 "06033C104JAT2A" 0603L#1 2713.44,2341.5 r180 top
C178 "06033C393KAT2A" 0603L#1 3927,1716 r90 top
C179 "06033C393KAT2A" 0603L#1 3783,1716 r90 top
C180 "GRM31CR61A226ME19L" 1206L 4433,1283 r180 top
C181 "GRM31CR61A226ME19L" 1206L 4433,1283 r180 bottom
C182 "GRM31CR61A226ME19L" 1206L 3325,1283 r0 top
C183 "GRM31CR61A226ME19L" 1206L 3325,1283 r0 bottom
C184 "EMK212BJ106KG-T" 0805L 3895.5,1319.27 r270 bottom
C185 "06033C104JAT2A" 0603L#1 3108.68,2418 r270 top
C186 "C1608X5R1A106M" 0603L#1 3400.68,2539 r270 top
C187 "06035A561JAT2A" 0603L#1 3207.68,2558.87 r270 bottom
C188 "C1608X5R1A106M" 0603L#1 2652,2406.01 r180 top
C189 "06033C104JAT2A" 0603L#1 2856.56,2341.5 r0 top
C190 "C1608X5R1A106M" 0603L#1 3299.41,1084 r0 bottom
C191 "06033C104JAT2A" 0603L#1 4453.5,2513.93 r270 top
C192 "GRM188R71C472KA01D" 0603L#1 4149,2536.39 r90 top
C193 "EEU-EB1E101S" CAPPR250W50D630H1120 1826,153.54 r270 top
C194 "GRM32DC81E106KA12L" 1210L 2037.3,73.49 r0 bottom
C195 "C1608X5R1A106M" 0603L#1 3108.68,2418 r270 bottom
C196 "C1608X5R1A106M" 0603L#1 4149,2402.53 r90 top
C197 "C1608X5R1A106M" 0603L#1 2856.56,2292.5 r0 top
C198 "06033C104JAT2A" 0603L#1 4197,2536.39 r90 top
C199 "06033C104JAT2A" 0603L#1 4458.59,1084 r180 top
C200 "C1608X5R1A106M" 0603L#1 3024.26,789.7 r0 top
C201 "C1608X5R1C105K" 0603L#1 329.24,689.56 r270 bottom
C202 "C1608X5R1A106M" 0603L#1 4453.5,2513.93 r270 bottom
C203 "C1608X5R1A106M" 0603L#1 4458.59,1084 r180 bottom
C204 "C1608X5R1A106M" 0603L#1 4197,2536.39 r90 bottom
C205 "C1608X5R1A105K" 0603L#1 3048,567 r90 bottom
C206 "C1005X5R1A104K" 0402L#1 1271.2,2316.76 r270 bottom
C207 "C1005X5R1A104K" 0402L#1 1153.09,2316.76 r270 bottom
C208 "C1005X5R1A104K" 0402L#1 1094.03,2316.76 r270 bottom
C209 "C1005X5R1A104K" 0402L#1 995.61,2316.76 r270 bottom
C210 "0603YC104JAT2A" 0603L#1 111.3,839 r0 bottom
C211 "C1608X5R1C105K" 0603L#1 228.7,775.86 r0 bottom
C212 "GRM31CR60J107ME39L" 1206 2933,846 r0 bottom
C213 "06033C104JAT2A" 0603L#1 2966,407.69 r270 bottom
C214 "C0603X5R0J104K" 0201#1 2940.59,781.24 r180 top
C215 "GRM155R71A104KA01D" 0402L#1 1498,1726 r180 top
C216 "GRM155R71A104KA01D" 0402L#1 1841,1842 r0 top
C217 "GRM155R71A104KA01D" 0402L#1 3050.55,1790 r180 top
C218 "GRM155R71A104KA01D" 0402L#1 2535,1040 r180 top
C219 "GRM155R71A104KA01D" 0402L#1 3208.85,1090 r180 top
C220 "GRM155R71A104KA01D" 0402L#1 3473,990 r0 bottom
C221 "GRM155R71A104KA01D" 0402L#1 3388,1090 r0 bottom
C222 "GRM155R71A104KA01D" 0402L#1 4554,1090 r0 top
C223 "GRM155R71A104KA01D" 0402L#1 4126,1090 r180 bottom
C224 "GRM155R71A104KA01D" 0402L#1 3204,1790 r180 bottom
C225 "GRM155R71A104KA01D" 0402L#1 3388,1790 r0 bottom
C226 "GRM155R71A104KA01D" 0402L#1 4342,1790 r0 bottom
C227 "GRM155R71A104KA01D" 0402L#1 4126,1790 r180 bottom
C228 "500R07S0R5BV4T" 0402L#1 730.85,1504.45 r270 bottom
C229 "500R07S0R5BV4T" 0402L#1 730.85,1431.46 r90 bottom
C230 "GRM1885C1H470JA01D" 0603L#1 2611.33,1739.79 r270 bottom
C231 "C1005X5R1A104K" 0402L#1 2574.33,1740.79 r90 bottom
C232 "C1005X5R0J105M" 0402L#1 2544.33,1740.79 r270 bottom
C233 "GRM1555C1H4R7CA01D" 0402L#1 2514.33,1740.79 r270 bottom
C234 "GRM1885C1H470JA01D" 0603L#2 2611.33,1739.79 r270 top
C235 "C1005X5R1A104K" 0402L#1 2574.33,1740.79 r90 top
C236 "C1005X5R0J105M" 0402L#1 2544.33,1740.79 r270 top
C237 "GRM1555C1H4R7CA01D" 0402L#1 2514.33,1740.79 r270 top
C238 "GRM1555C1H4R7CA01D" 0402L#1 2418.24,1614.68 r0 top
C239 "GRM155R71E103KA01D" 0402L#1 2418.24,1584.68 r0 top
C240 "C1005X5R0J105M" 0402L#1 2418.24,1554.68 r0 top
C241 "GRM1555C1H4R7CA01D" 0402L#1 2340.24,1614.68 r180 top
C242 "GRM155R71E103KA01D" 0402L#1 2340.24,1584.68 r180 top
C243 "C1005X5R0J105M" 0402L#1 2340.24,1554.68 r180 top
C244 "GRM1555C1H561JA01D" 0402L#1 2568.29,1619.31 r180 top
C245 "GRM1555C1H470JA01D" 0402L#1 2568.29,1658.68 r180 top
C246 "GRM1555C1H4R7CA01D" 0402L#1 2528.92,1547.31 r180 top
C247 "GRM1555C1H2R2CA01D" 0402L#2 2528.92,1443 r180 top
C248 "GRM1555C1H4R7CA01D" 0402L#1 2283.02,1616 r270 top
C249 "GRM1555C1H220JA01D" 0402L#1 2509.33,1813.69 r0 top
C250 "C1005X5R1A104K" 0402L#1 2339,2179.37 r0 top
C251 "C1005X5R1A104K" 0402L#1 2509.33,1844 r0 top
C252 "C1005X5R0J105M" 0402L#1 2407.43,1989.09 r0 top
C253 "GRM155R71E103KA01D" 0402L#1 2407.43,1959.09 r0 top
C254 "GRM1555C1H270JA01D" 0402L#1 2407.43,1929.09 r0 top
C255 "C1005X5R0J105M" 0402L#1 2257.04,1989.09 r180 top
C256 "GRM155R71E103KA01D" 0402L#1 2257.04,1959.09 r180 top
C257 "GRM1555C1H270JA01D" 0402L#1 2257.04,1929.09 r180 top
C258 "C1005X5R1A104K" 0402L#1 1649.16,1544.09 r0 top
C259 "C1005X5R1A104K" 0402L#1 1316.91,2564.56 r270 top
C260 "C1005X5R1A104K" 0402L#3 1132,2537.87 r0 bottom
C261 "GRM155R71A104KA01D" 0402L#1 5244,1790 r0 top
C262 "GRM033R61A472KA01D" 0201#2 833.57,1441.46 r270 top
C263 "GRM033R61A472KA01D" 0201#2 833.57,1494.45 r90 top
D2 "1N4148W-7-F" SOD-123 2617.48,1165 r180 bottom
D4 "1N4148W-7-F" SOD-123 2617.48,1115 r180 top
D11 "MBRS540T3G" SMC 4099,1191 r0 top
D12 "MBRS540T3G" SMC 3611,1191 r180 top
DEVCLK "SASF546-P26-X1" CONN_LTI_SASF546-P26-X1 408.31,2322 r0 top
EXT5V_FMC12V "PBC03SAAN" PBC03SAAN 4746,90 r0 top
EXT_VCO "SASF546-P26-X1" CONN_LTI_SASF546-P26-X1 2222.02,1040 r270 top
FID1 "Fiducial" Fiducial10-30 341,2592 r0 top
FID2 "Fiducial" Fiducial10-30 88,478 r0 top
FID3 "Fiducial" Fiducial10-30 5651,2592 r0 top
FMC_RX1 "ASP-134488-01" CONN_SEARAY_ASP-134488-01 5419,1341.94 r90 bottom locked
FTDI_3P3V "TSW-103-07-G-S" TSW-103-07-G-S 1617.28,426 r180 top
GND "5011" Keystone5011 336.21,1945 r0 top
GND1 "5011" Keystone5011 2591,2576 r0 top
GND2 "5011" Keystone5011 5048,95 r0 top
GND3 "5011" Keystone5011 4647,2526 r0 top
H3 "1648-440-AL" Keystone_1902C 542,580 r180 bottom
H4 "1648-440-AL" Keystone_1902C 1843.5,2505 r180 bottom
H5 "NY PMS 440 0025 PH" "NY PMS 440 0025 PH"#1 542,580 r0 top
H6 "NY PMS 440 0025 PH" "NY PMS 440 0025 PH"#2 1843.5,2505 r0 top
J1 "TSW-104-07-G-S" TSW-104-07-G-S 3952,690 r270 top
J2 "TSW-102-07-G-S" TSW-102-07-G-S 2732,1415 r180 top
J3 "TSW-102-07-G-S" TSW-102-07-G-S 3401,690 r90 top
"KC705 JTAG" "TSW-102-07-G-S" TSW-102-07-G-S 4910,915 r180 top
L1 "BLM15HG102SN1D" 0402L#1 2010.36,1790 r0 bottom
L2 "BLM18SG331TN1D" 0603 1342.42,1932.5 r180 bottom
L3 "BLM18SG331TN1D" 0603 1139.46,2396.5 r0 bottom
L4 "BLM18SG331TN1D" 0603 1373.92,2035.92 r90 bottom
L5 "BLM18SG331TN1D" 0603 1034.98,2428 r270 bottom
L6 "BLM18SG260TN1D" 0603 3820,1908 r270 top
L7 "BLM18SG121TN1D" 0603 5000,1739.21 r0 top
L8 "CDRH6D28NP-3R0NC" CDRH6D28 4749,1614 r90 top
L9 "BLM18SG260TN1D" 0603 3000.5,1940 r180 top
L10 "BLM18SG260TN1D" 0603 2932,2134.5 r90 top
L11 "MSS1038-702NLB" MSS1038 4319,1571 r180 top
L12 "744325550" WE-HC6 3368,1571 r180 top
L13 "BLM18SG260TN1D" 0603 2860,2071.5 r90 top
L14 "BLM18SG121TN1D" 0603 3271.85,1175 r270 top
L15 "BLM18SG260TN1D" 0603 2741,2437.5 r270 top
L16 "BLM18SG260TN1D" 0603 2829,2437.5 r270 top
L17 "BLM18SG260TN1D" 0603 1952.65,202.76 r0 bottom
L18 "BLM18SG260TN1D" 0603 4417,2602.93 r0 top
L19 "BLM18SG331TN1D" 0603 1373.92,2218.71 r270 bottom
L20 "BLM18SG121TN1D" 0603 4486.15,1175 r270 top
L21 "BLM18SG331TN1D" 0603 875.5,2247.39 r270 bottom
L22 "BLM18SG331TN1D" 0603 875.5,2030.86 r270 bottom
L23 "BLM18SG331TN1D" 0603 3166,251 r0 top
L24 "BLM18SG121TN1D" 0603 2659,491 r180 bottom
L25 "BLM18SG121TN1D" 0603L#1 2598.56,682 r270 bottom
L26 "BLM18SG260TN1D" 0603 115.24,775.86 r180 bottom
L27 "BLM15HG102SN1D" 0402L#1 2649,1710.99 r90 bottom
L28 "BLM15HG102SN1D" 0402L#4 2667.84,1733.13 r180 top
L29 "BLM15HG102SN1D" 0402L#1 2398.55,1502.68 r90 top
L30 "BLM15HG102SN1D" 0402L#1 2359.92,1502.68 r90 top
L31 "BLM15HG102SN1D" 0402L#1 2882,1415 r180 top
L32 "BLM15HG102SN1D" 0402L#1 2407.43,2019.09 r180 top
L33 "BLM15HG102SN1D" 0402L#1 2257.04,2019.09 r0 top
L34 "BLM15HG102SN1D" 0402L#1 2084,1620.82 r180 bottom
LBL1 "Size: 0.65\" x 0.20 \"" Label_650x200 4825,2178 r90 bottom
LD "LTST-C190GKT" LED_LTST-C190 2329.16,2235.37 r180 top
LD1 "TESTPOINT" TESTPOINT#1 1587.93,2181 r270 top
LD2 "TESTPOINT" TESTPOINT#1 724,2561 r180 top
LF1 "C1608C0G1E392J" 0603L#1 955.3,2436.74 r180 top
LF2 "06035A470JAT2A" 0603L#1 955.3,2386.74 r180 top
LF3 "RC0603FR-07619RL" 0603L#1 875.86,2409.18 r90 top
LF7 "ACM7060-301-2PL-TL" IND_TDK_ACM7060 1498.5,153.54 r0 bottom
LMK_INT "TSW-102-07-G-S" TSW-102-07-G-S 3645,2040 r180 top
LMK_LDO "TSW-102-07-G-S" TSW-102-07-G-S 3082,2040 r180 top
LMKCLK "SASF546-P26-X1" CONN_LTI_SASF546-P26-X1 1517.5,2482.51 r0 top
LMX_INT "TSW-102-07-G-S" TSW-102-07-G-S 4433,2040 r180 top
LMX_LDO "TSW-102-07-G-S" TSW-102-07-G-S 3870,2040 r180 top
LO2_N "TESTPOINT" TESTPOINT#2 2079.05,1833.99 r90 top
LO2_P "TESTPOINT" TESTPOINT#2 2079.05,1796.01 r90 top
LO3_N "TESTPOINT" TESTPOINT#2 2129.32,1728 r90 top
LO3_P "TESTPOINT" TESTPOINT#2 2092.69,1728 r90 top
Logo1 "ESD Susceptible" ESD_Overlay_Small 4854,1930 r0 top
Logo2 "Texas Instruments" TI_Symbol_Overlay_Small 4640,2277 r0 top
NCO "TSW-103-07-G-D" TSW-103-07-G-D 1871.5,1140 r0 top
OR "TSW-103-07-G-S" TSW-103-07-G-S 1555.5,2015 r180 top
OR_T0 "LTST-C190KFKT" LED_LTST-C190 3013,1232.52 r0 top
OR_T1 "LTST-C190KFKT" LED_LTST-C190 3013,1090 r0 top
OSCin "SASF546-P26-X1" CONN_LTI_SASF546-P26-X1 2599.24,2125 r0 top
PG_RX1 "TSW-102-07-G-S" TSW-102-07-G-S 4944,2559 r180 top
R1 "CRCW04028K06FKED" 0402L#1 2896,1140 r0 bottom
R2 "CRCW04021K20JNED" 0402L#1 3042.53,1212.84 r270 bottom
R3 "CRCW04021M00JNED" 0402L#1 2787,1254.36 r0 bottom
R4 "CRCW060310K0FKEA" 0603L#1 2418.5,1090 r180 top
R5 "CRCW060310K0FKEA" 0603L#1 1871.5,1004 r90 bottom
R6 "CRCW060310K0FKEA" 0603L#1 1771.5,1004 r90 bottom
R7 "ERJ-1GE0R00C" 0201#1 1583.2,1224.93 r90 bottom
R8 "ERJ-1GE0R00C" 0201#1 1493.2,1165.87 r90 bottom
R9 "ERJ-1GE0R00C" 0201#1 1264.85,1010.18 r0 bottom
R10 "CRCW04021K20JNED" 0402L#1 3042.53,1109.68 r90 bottom
R11 "CRCW04021M00JNED" 0402L#1 2742.32,950 r0 top
R12 "CRCW04021K33FKED" 0402L#1 2817.32,1122 r0 bottom
R13 "RG1608P-332-B-T5" 0603L#1 936.26,1175 r180 top
R14 "CRCW060310K0FKEA" 0603L#1 1731.28,858.81 r0 top
R15 "CRCW060310K0FKEA" 0603L#1 1731.28,811.41 r0 top
R16 "CRCW060310K0FKEA" 0603L#1 1731.28,763.41 r0 top
R17 "RC0603JR-07750RL" 0603L#1 1731.28,763.41 r0 bottom
R18 "ERJ-1GE0R00C" 0201#1 1080.99,1694 r90 bottom
R19 "ERJ-1GE0R00C" 0201#1 1080.99,1694 r90 top
R20 "ERJ-1GE0R00C" 0201#1 1107.99,1694 r90 top
R21 "ERJ-1GE0R00C" 0201#1 1107.99,1694 r90 bottom
R22 "ERJ-1GE0R00C" 0201#1 1094,1653 r0 top
R23 "ERJ-1GE0R00C" 0201#1 1135,1666 r270 top
R24 "CRCW040210K0FKED" 0402L#1 2509.33,1879.09 r0 top
R25 "ERJ-2GE0R00X" 0402L#1 2529.02,1931.09 r270 top
R26 "ERJ-2GE0R00X" 0402L#1 2976.47,1659.68 r270 top
R27 "CRCW0402100RFKED" 0402L#1 2030.05,1939.5 r270 top
R28 "CRCW0402100RFKED" 0402L#1 2029.05,1640.5 r90 top
R29 "ERJ-2GE0R00X" 0402L#1 1926.05,1939.5 r270 top
R30 "CRCW040249R9FKED" 0402L#1 2489.65,1931.09 r90 top
R31 "RC0603JR-071K3L" 0603L#1 1731.28,811.41 r0 bottom
R32 "RC0603JR-071K3L" 0603L#1 1731.28,858.81 r0 bottom
R33 "CRCW04023K30JNED" 0402L#1 1926.05,1640.5 r90 bottom
R34 "CRCW0402100RFKED" 0402L#1 2030.05,1863.5 r90 top
R35 "CRCW0402100RFKED" 0402L#1 2029.05,1716.5 r270 top
R36 "ERJ-2GE0R00X" 0402L#1 1926.05,1863.5 r90 top
R37 "CRCW04023K30JNED" 0402L#1 1926.05,1716.5 r270 bottom
R38 "ERJ-2GE0R00X" 0402L#1 2588,1813.68 r0 top
R39 "RC0603JR-071KL" 0603L#1 3191,1940 r0 top
R40 "CSNL1206FT2L00" 1206 3082,2135.44 r180 bottom
R41 "CRCW060310K7FKEA" 0603L#1 3218,2065 r90 bottom
R42 "CSNL1206FT2L00" 1206 3645,2135.44 r180 bottom
R43 "CRCW04020000Z0ED" 0402L#1 796.78,2106 r180 top
R44 "CRCW04020000Z0ED" 0402L#1 796.78,2140 r180 top
R45 "CRCW0603270RJNEA" 0603L#1 826.5,2625 r0 top
R47 "RC0603FR-072K32L" 0603L#1 1057.79,1890 r180 bottom
R48 "CRCW04020000Z0ED" 0402L#1 1281.67,2488.35 r0 top
R49 "RC0603FR-074K64L" 0603L#1 3293,2037.44 r180 bottom
R50 "Used in BOM report" 0402L#1 1204.98,2489 r180 top
R51 "CRCW040251R0JNED" 0402L#1 1338.67,2462.82 r90 top
R52 "CRCW060310R0JNEA" 0603L#1 957.8,531.69 r0 top
R53 "CRCW060310R0JNEA" 0603L#1 957.8,483.69 r0 top
R54 "CRCW0603100RJNEA" 0603L#1 4260.56,263.94 r270 bottom
R55 "CRCW0603100RJNEA" 0603L#1 4205.44,263.94 r270 bottom
R56 "CRCW0603270RJNEA" 0603L#1 1653.5,2267.95 r180 top
R57 "CRCW0603100RJNEA" 0603L#1 4205.44,487.44 r90 bottom
R58 "CRCW0603100RJNEA" 0603L#1 4260.56,466.06 r90 bottom
R59 "CRCW04020000Z0ED" 0402L#1 1413.56,2164 r0 top
R60 "CRCW04020000Z0ED" 0402L#1 1413.56,2130 r0 top
R61 "CRCW04020000Z0ED" 0402L#1 1238.98,1857 r270 top
R62 "CRCW04020000Z0ED" 0402L#1 1204.98,1857 r270 top
R63 "CRCW04020000Z0ED" 0402L#1 1002.76,1857 r270 top
R64 "CRCW04020000Z0ED" 0402L#1 968.76,1857 r270 top
R65 "CRCW0603100RJNEA" 0603L#1 4069.68,229 r0 top
R66 "CRCW06031K00FKEA" 0603L#1 2508.47,351.73 r180 top
R67 "RC0603FR-0712KL" 0603L#1 2456.47,575.52 r270 top
R68 "CRCW0603100RJNEA" 0603L#1 3323.44,440 r180 top
R69 "CRCW0603100RJNEA" 0603L#1 3426,440 r0 bottom
R70 "RC0603JR-0710KL" 0603L#1 4726.19,1164.85 r270 bottom
R71 "RC0603JR-071KL" 0603L#1 3979,1940 r0 top
R72 "CRCW060382K5FKEA" 0603L#1 4772.44,995 r0 top
R73 "CSNL1206FT2L00" 1206 3870,2135.44 r180 bottom
R74 "CRCW060310K7FKEA" 0603L#1 4006,2065 r90 bottom
R75 "CSNL1206FT2L00" 1206 4433,1944.56 r180 bottom
R76 "CRCW060322K1FKEA" 0603L#1 4881,995 r180 top
R77 "RC0603FR-074K64L" 0603L#1 4081,2037.44 r180 bottom
R78 "RC0603FR-0710RL" 0603L#1 3879,1716 r270 top
R79 "CRCW0603732RFKEA" 0603L#1 3449.68,2539 r270 top
R80 "RC0603JR-071KL" 0603L#1 3365.66,2631 r180 top
R81 "CRCW060316K2FKEA" 0603L#1 4023,1716 r270 bottom
R82 "CRCW06037K87FKEA" 0603L#1 3687,1716 r90 bottom
R83 "CSNL1206FT2L00" 1206 3280.26,2209.56 r0 bottom
R84 "CSNL1206FT2L00" 1206 2973.27,2564.44 r180 bottom
R85 "CRCW06032K49FKEA" 0603L#1 3108.68,2520 r270 top
R86 "CRCW06035K90FKEA" 0603L#1 3975,1716 r270 top
R87 "CRCW06035K90FKEA" 0603L#1 3735,1716 r270 top
R88 "CRCW06034K99FKEA" 0603L#1 3132.68,2547.56 r180 bottom
R89 "CRCW06032K80FKEA" 0603L#1 3310.36,2558.87 r90 bottom
R90 "RC0603FR-07402RL" 0603L#1 3400.68,2539 r90 bottom
R91 "CRCW04024K99FKED" 0402L#1 2587.98,1567 r270 top
R92 "CSNL1206FT2L00" 1206 4380.44,2552.93 r90 bottom
R93 "RC0603FR-071KL" 0603L#1 4149,2536.39 r270 bottom
R94 "CRCW12061K00JNEA" 1206L 4746,289 r270 top
R95 "CSNL1206FT2L00" 1206 4329.44,2319.07 r90 bottom
R96 "RC0603FR-07357RL" 0603L#1 4173,2612 r180 top
R97 "CRCW060312K4FKEA" 0603L#1 3426,540 r0 top
R98 "CRCW060312K4FKEA" 0603L#1 3426,440 r0 top
R99 "ERJ-3GEY0R00V" 0603L#1 1361,737 r0 bottom
R100 "ERJ-3GEY0R00V" 0603L#1 1361,817 r0 bottom
R101 "CRCW060312K4FKEA" 0603L#1 3426,340 r0 top
R102 "CRCW060312K4FKEA" 0603L#1 3426,240 r0 top
R103 "CRCW06030000Z0EA" 0603L#1 329.24,811.96 r270 bottom
R104 "CRCW040224K0JNED" 0402L#1 3418.13,398 r180 top
R105 "CRCW060310K0FKEA" 0603L#1 2817.32,735 r90 bottom
R106 "CRCW060310K0FKEA" 0603L#1 2754.2,815 r90 top
R107 "CRCW060310K0FKEA" 0603L#1 2706.2,815 r90 top
R108 "RC0603JR-072K2L" 0603L#1 2844.88,659 r180 bottom
R109 "CRCW0603100RJNEA" 0603L#1 4233,438.5 r180 top
R110 "CRCW0603100RJNEA" 0603L#1 4233,340.5 r180 top
R111 "CRCW0603100RJNEA" 0603L#1 4233,389.5 r180 top
R112 "CRCW0603270RJNEA" 0603L#1 2416.91,273.24 r270 top
R113 "CRCW0603100RJNEA" 0603L#1 3324,540 r180 top
R114 "CRCW0603100RJNEA" 0603L#1 3323.44,298 r180 top
R115 "CRCW0603100RJNEA" 0603L#1 3370.88,157.56 r180 top
R116 "CRCW040224K0JNED" 0402L#1 3371.24,498 r180 top
R117 "CRCW0603100RJNEA" 0603L#1 3060.26,392.13 r180 bottom
R118 "CRCW0603100RJNEA" 0603L#1 4233,291.5 r180 top
R119 "CRCW0603100RJNEA" 0603L#1 3426,540 r0 bottom
R120 "CRCW0603100RJNEA" 0603L#1 3426,340 r0 bottom
R121 "CRCW0603100RJNEA" 0603L#1 3426,240 r0 bottom
R122 "RC0603JR-071K3L" 0603L#1 1028.93,1966.24 r270 bottom
R123 "CRCW060310K0FKEA" 0603L#1 4157,290.53 r270 top
R124 "CRCW0603100RJNEA" 0603L#1 3163,369.57 r270 top
R125 "CRCW0603100RJNEA" 0603L#1 3214.56,369.57 r270 top
R126 "CRCW0603100RJNEA" 0603L#1 3191,445 r0 top
R127 "CRCW0603100RJNEA" 0603L#1 3242.12,397.13 r0 bottom
R128 "CRCW040224K0JNED" 0402L#1 3418.13,298 r180 top
R129 "CRCW040224K0JNED" 0402L#1 3418.13,282 r180 bottom
R130 "CRCW060310K0FKEA" 0603L#1 3206,522.46 r270 bottom
R131 "CRCW060310K0FKEA" 0603L#1 3157,542.15 r270 bottom
R132 "CRCW06030000Z0EA" 0603L#1 5026,515 r0 top
R133 "CRCW04021K00FKED" 0402L#1 2829.24,1640 r180 bottom
R134 "RC0603JR-071KL" 0603L#1 1356,1754 r180 bottom
R135 "CRCW06032K10FKEA" 0603L#1 1376.64,1678.24 r90 bottom
R136 "CRCW06034K70JNEA" 0603L#1 1821.5,1302 r90 top
R137 "CRCW06034K70JNEA" 0603L#1 1949.06,1276 r0 top
R138 "CRCW06034K70JNEA" 0603L#1 2418.5,1040 r0 top
R139 "CRCW06032K00JNEA" 0603L#1 4519.44,292.56 r270 bottom
R140 "CRCW06032K00JNEA" 0603L#1 4519.44,392.56 r270 bottom
R141 "CRCW06032K00JNEA" 0603L#1 4519.44,492.56 r270 bottom
R142 "ERJ-3GEY0R00V" 0603L#1 1356,1843 r180 bottom
R143 "ERJ-3GEY0R00V" 0603L#1 1356,1798.5 r180 bottom
R144 "CRCW040210K0FKED" 0402L#5 2528.92,1588 r0 top
R145 "ERJ-2GE0R00X" 0402L#6 2509.24,1639 r270 top
R146 "ERJ-2GE0R00X" 0402L#1 2450,1432.5 r0 top
R147 "ERJ-2GE0R00X" 0402L#1 2450,1397.5 r180 top
R148 "ERJ-2GE0R00X" 0402L#6 2548.61,1494 r270 top
R149 "ERJ-2GE0R00X" 0402L#5 2496.24,1494 r90 top
R150 "CRCW04021M00JNED" 0402L#1 2587.98,1494 r90 top
R151 "CRCW06030000Z0EA" 0603L#1 2173,1615 r0 top
R152 "CRCW06030000Z0EA" 0603L#1 2173,1565 r180 top
R153 "CRCW040249R9FKED" 0402L#1 2263.34,1540 r0 top
R154 "CRCW040215K0JNED" 0402L#1 2395,2159.68 r270 top
R156 "CRCW0402127RFKED" 0402L#1 1278.36,2519 r0 bottom
R157 "CRCW0402127RFKED" 0402L#1 1204.98,2519 r180 bottom
R158 "CRCW040282R5FKED" 0402L#1 1278.36,2489 r180 bottom
R159 "CRCW040282R5FKED" 0402L#1 1204.98,2489 r0 bottom
R160 "CRCW04020000Z0ED" 0402L#1 796.79,2193.37 r180 top
R161 "CRCW04020000Z0ED" 0402L#1 796.79,2227.37 r180 top
R162 "CRCW0402107RFKED" 0402L#7 1926.05,1678.5 r270 top
R163 "CRCW04022K20JNED" 0402L#1 1957.36,1640.5 r270 bottom
R164 "CRCW04022K20JNED" 0402L#1 1957.36,1716.5 r90 bottom
R165 "CRCW040251R0JNED" 0402L#1 388.62,2141.68 r0 top
R166 "CRCW0402560RJNED" 0402L#1 853.24,2123 r270 top
R167 "CRCW0402560RJNED" 0402L#1 853.24,2210.37 r270 top
RR6 "CRCW06034K99FKEA" 0603L#1 5321.56,2340 r180 top
RR7 "ERJ-3GEY0R00V" 0603L#1 5269,390 r180 top
RSV "TSW-103-07-G-S" TSW-103-07-G-S 1045.28,702 r0 top
S1 "L101011MS02Q" "SW_ L101011MS02Q" 1065,212.6 r270 top
SH-1V2ADC_INT_1_2 "SNT-100-BK-G" SNT-100-BK-G 3280.26,2305 r180 top
SH-1V2ADC_LDO_1_2 "SNT-100-BK-G" SNT-100-BK-G 2973.27,2469 r180 top
SH-1V9ADC_1_2 "SNT-100-BK-G" SNT-100-BK-G 4285,2552.93 r90 top
SH-1V9INT_1_2 "SNT-100-BK-G" SNT-100-BK-G 4234,2319.07 r90 top
SH-5V_12V_1_2 "SNT-100-BK-G" SNT-100-BK-G 4696,90 r180 top
SH-FTDI_3P3V_1_2 "SNT-100-BK-G" SNT-100-BK-G 1567.28,426 r0 top
SH-J2_1_2 "SNT-100-BK-G" SNT-100-BK-G 2732,1415 r180 top
SH-LMK_INT_1_2 "SNT-100-BK-G" SNT-100-BK-G 3645,2040 r180 top
SH-LMK_LDO_1_2 "SNT-100-BK-G" SNT-100-BK-G 3082,2040 r180 top
SH-LMX_INT_1_2 "SNT-100-BK-G" SNT-100-BK-G 4433,2040 r180 top
SH-LMX_LDO_1_2 "SNT-100-BK-G" SNT-100-BK-G 3870,2040 r180 top
SH-RSV_1_2 "969102-0000-DA" SNT-100-BK-G 995.28,702 r0 top
"SH-Ts ADD1_1_2" "969102-0000-DA" SNT-100-BK-G 1667.28,653 r180 top
SPI "TSW-104-07-G-D" TSW-104-07-G-D 4396,365 r90 top
Status1 "LTST-C190GKT" LED_LTST-C190 1523.5,2274.95 r0 top
Status2 "LTST-C190GKT" LED_LTST-C190 824.53,2561 r0 top
T1 "B0430J50100AHF" B0430J50100AHF 713.33,1330.16 r0 bottom
T2 "TCM2-43X+" Mini-Circuits-DB1627 605.65,1467.95 r270 bottom
TCRIT1 "TESTPOINT" TESTPOINT#1 1836.28,653 r270 top
TCRIT2 "TESTPOINT" TESTPOINT#1 1939.5,725 r270 top
TCRIT3 "TESTPOINT" TESTPOINT#1 1703.72,937 r270 top
Tdiode "TSW-102-07-G-S" TSW-102-07-G-S 1270.28,777 r270 top
TEMP "LTST-C170KRKT" LED_LTST-C170 1833.28,817.94 r270 top
TMST+ "142-0701-806" Johnson_142-0701-80x 100,1830.16 r270 bottom
TMST- "142-0701-806" Johnson_142-0701-80x 100,2330.16 r270 bottom
"Ts ADD1" "TSW-103-07-G-S" TSW-103-07-G-S 1617.28,653 r180 top
U1 "LMC6762AIMX/NOPB" M08A_L 2837,1140 r270 top
U2 "ADC12J4000NKE" RLY0068A 1163.39,1340 r0 bottom
U3 "LM95233CISD/NOPB" SDA14B 1546.28,796.76 r0 top
U4 "TRF3765IRHB" RHB0032E 2332.24,1790 r270 top
U5 "LP3878MR-ADJ/NOPB" MRA08A_N 3388,2015 r180 top
U6 "LMK04828BISQ/NOPB" NKD0064A 1123.56,2147 r90 top
U7 "TPS54327DDA" DDA0008B_L 4825,1206 r90 top
U8 "LP3878MR-ADJ/NOPB" MRA08A_N 4176,2015 r180 top
U9 "LM26400YSDE/NOPB" SDA16A 3855,1524 r270 top
U10 "TPS74901RGW" RGW0020A 3254.68,2488 r90 top
U11 "LP38513TJ-ADJ/NOPB" TJ5A_N 3817,2436 r180 top
U12 "SN74AVC4T774PW" PW0016A_L 3987,365.53 r0 top
U13 "FT4232HL" LQFP64_N 2835.47,488 r0 top
U14 "TLV70233DBV" DBV0005A_N 228.7,670.86 r180 bottom
U15 "93LC46B-I/MS" MSOP-MS8_N 2900,567 r0 bottom
U16 "24C65T/SM" SOIJ-SM8_N 4208,765 r180 top
U17 "MC10EP32D" 751-06_N 1763.33,1678.5 r180 top
U18 "SN74LVC1G125DBV" SOP-5_.95MM_(DBV) 2864.68,384.9 r90 bottom
USB "651-305-142-821" CONN_USB-MINI-AB-651-305-142-821 220.47,782.44 r270 top
USB_PWR "LTST-C190GKT" LED_LTST-C190 2480.91,275.2 r270 top
uWIRE "N2510-6002-RB" CONN_2510-6002 3656,440 r90 top
VA12 "TSW-102-07-G-S" TSW-102-07-G-S 2461,2431 r180 top
VA19 "TSW-102-07-G-S" TSW-102-07-G-S 1145.28,927 r90 top
VADJ_RX "5011" Keystone5011 4994,2315 r90 top
Vbg "TSW-102-07-G-S" TSW-102-07-G-S 982.78,927 r90 top
Vcmo "TSW-102-07-G-S" TSW-102-07-G-S 857.78,927 r90 top
VD12 "TSW-102-07-G-S" TSW-102-07-G-S 1423,1078 r180 top
VIN "142-0701-806" Johnson_142-0701-80x 100,1330.16 r270 bottom
VIN+ "SASF546-P26-X1" CONN_LTI_SASF546-P26-X1 580,963.32 r0 top
VIN- "SASF546-P26-X1" CONN_LTI_SASF546-P26-X1 580,1697 r0 top
Vtune "TESTPOINT" TESTPOINT#3 2626.24,1513.68 r180 top
Y1 "CWX813-100.0M" OSC_CWX 2829.24,1740 r180 top
Y2 "ABM3-12.000MHZ-B2-T" XTAL_ABM3 2501.47,827 r180 top
ZZ1 "This Assembly Note is for PCB labels only" AssemblyNoteLabel 185,3938 r0 top
ZZ2 "These assemblies are ESD sensitive, ESD precautions shall be observed." AssemblyNote 185,3829.11 r0 top
ZZ3 "These assemblies must be clean and free from flux and all contaminants. Use of no clean flux is not acceptable." AssemblyNote 185,3740.56 r0 top
ZZ4 "These assemblies must comply with workmanship standards IPC-A-610 Class 2., unless otherwise specified." AssemblyNote 185,3652 r0 top

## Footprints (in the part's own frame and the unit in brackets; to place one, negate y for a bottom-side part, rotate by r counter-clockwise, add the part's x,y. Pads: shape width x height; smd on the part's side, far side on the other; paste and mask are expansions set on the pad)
0201#1 [mm] "Data from Kemet datasheet CC101_COM dated 7/28/11"
  rect 0.46x0.42 smd mask+0.048: 1(-0.33,0) 2(0.33,0)
  body extent -0.31,-0.16 0.31,0.16, height 0.26
0201#2 [mm] "Data from Kemet datasheet CC101_COM dated 7/28/11"
  rect 0.42x0.46 smd mask+0.048: 1(-0.33,0)
  rect 0.46x0.42 smd mask+0.048: 2(0.33,0)
  body extent -0.31,-0.16 0.31,0.16, height 0.26
0201L [mm] "Data from Kemet datasheet CC101_COM dated 7/28/11"
  rect 0.36x0.32 smd mask+0.048: 1(-0.28,0) 2(0.28,0)
  body extent -0.31,-0.16 0.31,0.16, height 0.26
0402L#1 [mm] "0402 from SM-752 data"
  rect 0.6x0.5 smd: 1(-0.5,0) 2(0.5,0)
  body extent -0.55,-0.3 0.55,0.3, height 0.6
0402L#2 [mm] "0402 from SM-752 data"
  rect 0.6x0.5 smd mask+0.071: 1(-0.5,0) 2(0.5,0)
  body extent -0.55,-0.3 0.55,0.3, height 0.6
0402L#3 [mm] "0402 from SM-752 data"
  rect 0.6x0.5 smd: 1(-0.5,0)
  rect 0.6x0.5 smd mask+0.075: 2(0.5,0)
  body extent -0.55,-0.3 0.55,0.3, height 0.6
0402L#4 [mm] "0402 from SM-752 data"
  rect 0.6x0.5 smd: 1(-0.5,0)
  rect 0.6x0.5 smd mask+0.053: 2(0.5,0)
  body extent -0.55,-0.3 0.55,0.3, height 0.6
0402L#5 [mm] "0402 from SM-752 data"
  rect 0.6x0.5 smd mask+0.071: 1(-0.5,0)
  rect 0.6x0.5 smd: 2(0.5,0)
  body extent -0.55,-0.3 0.55,0.3, height 0.6
0402L#6 [mm] "0402 from SM-752 data"
  rect 0.6x0.5 smd: 1(-0.5,0)
  rect 0.6x0.5 smd mask+0.071: 2(0.5,0)
  body extent -0.55,-0.3 0.55,0.3, height 0.6
0402L#7 [mm] "0402 from SM-752 data"
  rect 0.6x0.5 smd mask+0.066: 1(-0.5,0) 2(0.5,0)
  body extent -0.55,-0.3 0.55,0.3, height 0.6
0603 [mm] "0603 from SM-752 data"
  rect 1x0.95 smd: 1(-0.8,0) 2(0.8,0)
  silkscreen extent -1.52,-0.69 1.52,0.69, body extent -0.87,-0.47 0.87,0.47, height 0.85
0603L#1 [mm] "0603 from SM-752 data"
  rect 0.8x0.85 smd: 1(-0.7,0) 2(0.7,0)
  silkscreen extent -0.07,-0.33 0.07,0.33, body extent -0.87,-0.47 0.87,0.47, height 0.85
0603L#2 [mm] "0603 from SM-752 data"
  rect 0.8x0.85 smd: 1(-0.7,0)
  rect 0.8x0.85 smd mask+0.053: 2(0.7,0)
  silkscreen extent -0.07,-0.33 0.07,0.33, body extent -0.87,-0.47 0.87,0.47, height 0.85
751-06_N [mm] "SOIC, 8-Leads, Body 4.9x3.9mm, Pitch 1.27mm, IPC Medium Density"
  oval 2.2x0.6 smd: 1(-2.4,1.905) 2(-2.4,0.635) 3(-2.4,-0.635) 4(-2.4,-1.905) 5(2.4,-1.905) 6(2.4,-0.635) 7(2.4,0.635) 8(2.4,1.905)
  silkscreen extent -2.53,-2.5 0.9,2.88, body extent -1.95,-2.45 1.95,2.45, height 1.75
0805L [mm] "0805 from SM-752 data"
  rect 1.1x1.4 smd: 1(-0.75,0) 2(0.75,0)
  body extent -1.1,-0.72 1.1,0.72, height 1.1
1206 [mm] "1206 from SM-752 data"
  rect 1.3x1.85 smd: 1(-1.45,0) 2(1.45,0)
  silkscreen extent -2.4,-1.21 2.4,1.21, body extent -1.7,-0.9 1.7,0.9, height 1.35
1206L [mm] "1206 from SM-752 data"
  rect 1.1x1.75 smd: 1(-1.35,0) 2(1.35,0)
  silkscreen extent -0.4,-0.78 0.4,0.77, body extent -1.7,-0.9 1.7,0.9, height 1.35
1210L [mm] "1210 from SM-752 data"
  rect 1.1x2.6 smd: 1(-1.35,0) 2(1.35,0)
  silkscreen extent -0.4,-1.2 0.4,1.2, body extent -1.7,-1.35 1.7,1.35, height 1.35
3528-21 [mm] "Medium Density IPC, based on SM-782 section 8.4"
  rect 1.95x2.25 smd: 1(-1.375,0) 2(1.375,0)
  silkscreen extent -2.66,-1.5 1.9,1.79, body extent -1.85,-1.5 1.85,1.5, height 2.1
AssemblyNote [mil] "Assembly Note"
AssemblyNoteLabel [mil] "Assembly Note for PCB Labels"
B0430J50100AHF [mm] "Anaren Ultra Low Profile 0805 Balun 50  to 100  Balanced"
  rect 0.75x0.41 smd mask+0.073: 1(-0.705,0.66) 2(-0.705,0) 3(-0.705,-0.66) 4(0.705,-0.66) 5(0.705,0) 6(0.705,0.66)
  silkscreen extent -0.69,-1.07 0.69,1.07, body extent -0.69,-1.07 0.69,1.07, height 0.75
CAPPR250W50D630H1120 [mm] "PANASONIC"
  rect 1.25x1.25 hole 0.75: 1(-1.25,0)
  round 1.25 hole 0.75: 2(1.25,0)
  silkscreen extent -3.4,-3.4 3.4,3.4, body extent -3.37,-3.39 3.4,3.39, height 12.21
CDRH6D28 [mm] "Sumida reommended land pattern"
  rect 2.65x7.3 smd: 1(-2.325,0) 2(2.325,0)
  silkscreen extent -4,-4 4,4, body extent -3.5,-3.5 3.5,3.5, height 3
CONN_2510-6002 [mm] "3M 2500 series TS-0770-L December 15, 2011"
  rect 1.65x1.65 hole 1.016 mask+0: 1(-5.08,-1.27)
  round 1.65 hole 1.016 mask+0: 2(-5.08,1.27) 3(-2.54,-1.27) 4(-2.54,1.27) 5(0,-1.27) 6(0,1.27) 7(2.54,-1.27) 8(2.54,1.27) 9(5.08,-1.27) 10(5.08,1.27)
  silkscreen extent -10.01,-4.17 10.01,4.47, body extent -10.01,-4.11 10.01,4.52, height 9.92
CONN_CUI-PJ-202AH [mm] "Conn_DC Jack"
  oval 1.5x4 hole 1 slot 3.5 at 90 deg: 1(0,0) 2(6,0)
  oval 4x1.5 hole 1 slot 3.5 at 0 deg: 3(3,4.7)
  silkscreen extent -0.7,-4.5 13.7,4.5, body extent -0.7,-4.5 13.7,4.9, height 11.02
CONN_LTI_SASF546-P26-X1 [mm]
  round 0.8 smd: 1(0,0)
  round 2.25 hole 1.5 mask+0.051: 2(-2.54,2.54) 3(-2.54,-2.54) 4(2.54,-2.54) 5(2.54,2.54)
  silkscreen extent -3.4,-3.4 3.4,3.4, body extent -3.17,-3.17 3.17,3.17, height 12.53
